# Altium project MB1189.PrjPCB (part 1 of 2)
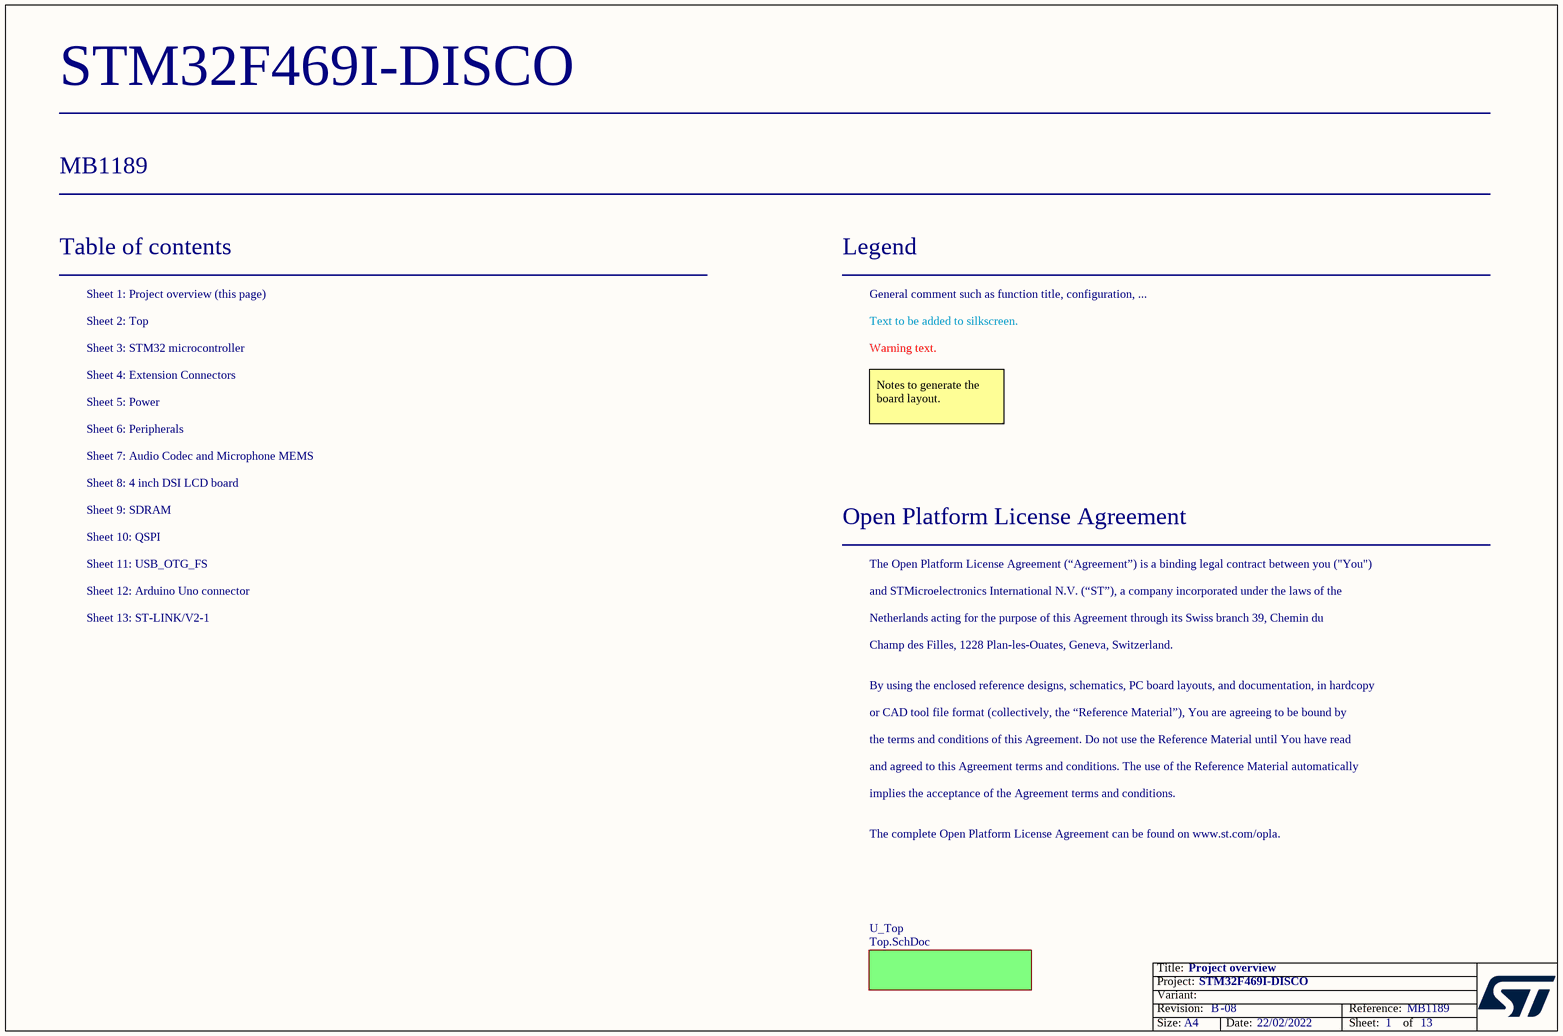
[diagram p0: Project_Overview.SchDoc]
Board_Reference: MB1189; Board_PCB_revision: B; Board_Name: STM32F469I-DISCO; Board_Document_Date: 22/02/2022; Board_Assembly_revision: 08
13 sheets, 276 parts. Net scope: flat (ports and power ports of the same name join across sheets).
Sheets:
  Project_Overview.SchDoc
    U_Top = Top.SchDoc
      U_Memory = Memory.SchDoc
      U_Peripherals = Peripherals.SchDoc
      U_Power = Power.SchDoc
      U_ST_LINK_V2-1 = ST_LINK_V2-1.SCHDOC
      U_MCU = MCU.SchDoc
      U_Arduino_ Connectors = Arduino_ Connectors.SchDoc
      U_DSI_LCD = DSI_LCD.SchDoc
      U_QSPI = QSPI.SchDoc
      U_AUDIO2 = AUDIO2.SchDoc
      U_USB_OTG_FS = USB_OTG_FS.SchDoc
      U_ExtensionConnector = ExtensionConnector.SchDoc

## Sheet Project_Overview.SchDoc: Project overview
size A4; Date: Not used; ApprovedBy: Not used; CheckedBy: Not used; Author: Not used; CompanyName: STMicroelectronics; DrawnBy: Not used; Engineer: Not used; Organization: Not used; Address1: Not used; Address2: Not used; Address3: Not used; Address4: Not used; DocumentNumber: 1; Revision: Not used; SheetNumber: 1; SheetTotal: 13

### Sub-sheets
U_Top = Top.SchDoc: no entries

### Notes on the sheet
- Table of contents
- Sheet 1: Project overview (this page)
- Legend
- General comment such as function title, configuration, ...
- Sheet 2: Top
- Sheet 3: STM32 microcontroller
- Sheet 4: Extension Connectors
- Text to be added to silkscreen.
- Warning text.
- Sheet 5: Power
- Sheet 6: Peripherals
- Notes to generate the board layout.
- Sheet 8: 4 inch DSI LCD board
- Sheet 7: Audio Codec and Microphone MEMS
- Sheet 9: SDRAM
- Sheet 11: USB_OTG_FS
- Sheet 10: QSPI
- Open Platform License Agreement
- The Open Platform License Agreement (“Agreement”) is a binding legal contract between you ("You")
- Sheet 13: ST-LINK/V2-1
- Sheet 12: Arduino Uno connector
- and STMicroelectronics International N.V. (“ST”), a company incorporated under the laws of the
- Netherlands acting for the purpose of this Agreement through its Swiss branch 39, Chemin du
- Champ des Filles, 1228 Plan-les-Ouates, Geneva, Switzerland.
- By using the enclosed reference designs, schematics, PC board layouts, and documentation, in hardcopy
- or CAD tool file format (collectively, the “Reference Material”), You are agreeing to be bound by
- the terms and conditions of this Agreement. Do not use the Reference Material until You have read
- and agreed to this Agreement terms and conditions. The use of the Reference Material automatically
- implies the acceptance of the Agreement terms and conditions.
- The complete Open Platform License Agreement can be found on www.st.com/opla.

## Sheet Top.SchDoc: MB1189
size A3; Date: 9/24/2014; Author: P.A.; CompanyName: STMicroelectronics; Organization: Microcontrollers Division; Address1: 12, Rue Jules HOROWITZ; Address2: 38019 Grenoble; Address3: FRANCE; DocumentNumber: 2; Revision: B-07; SheetNumber: 2; SheetTotal: 13; Project: STM32F469I-DISCO
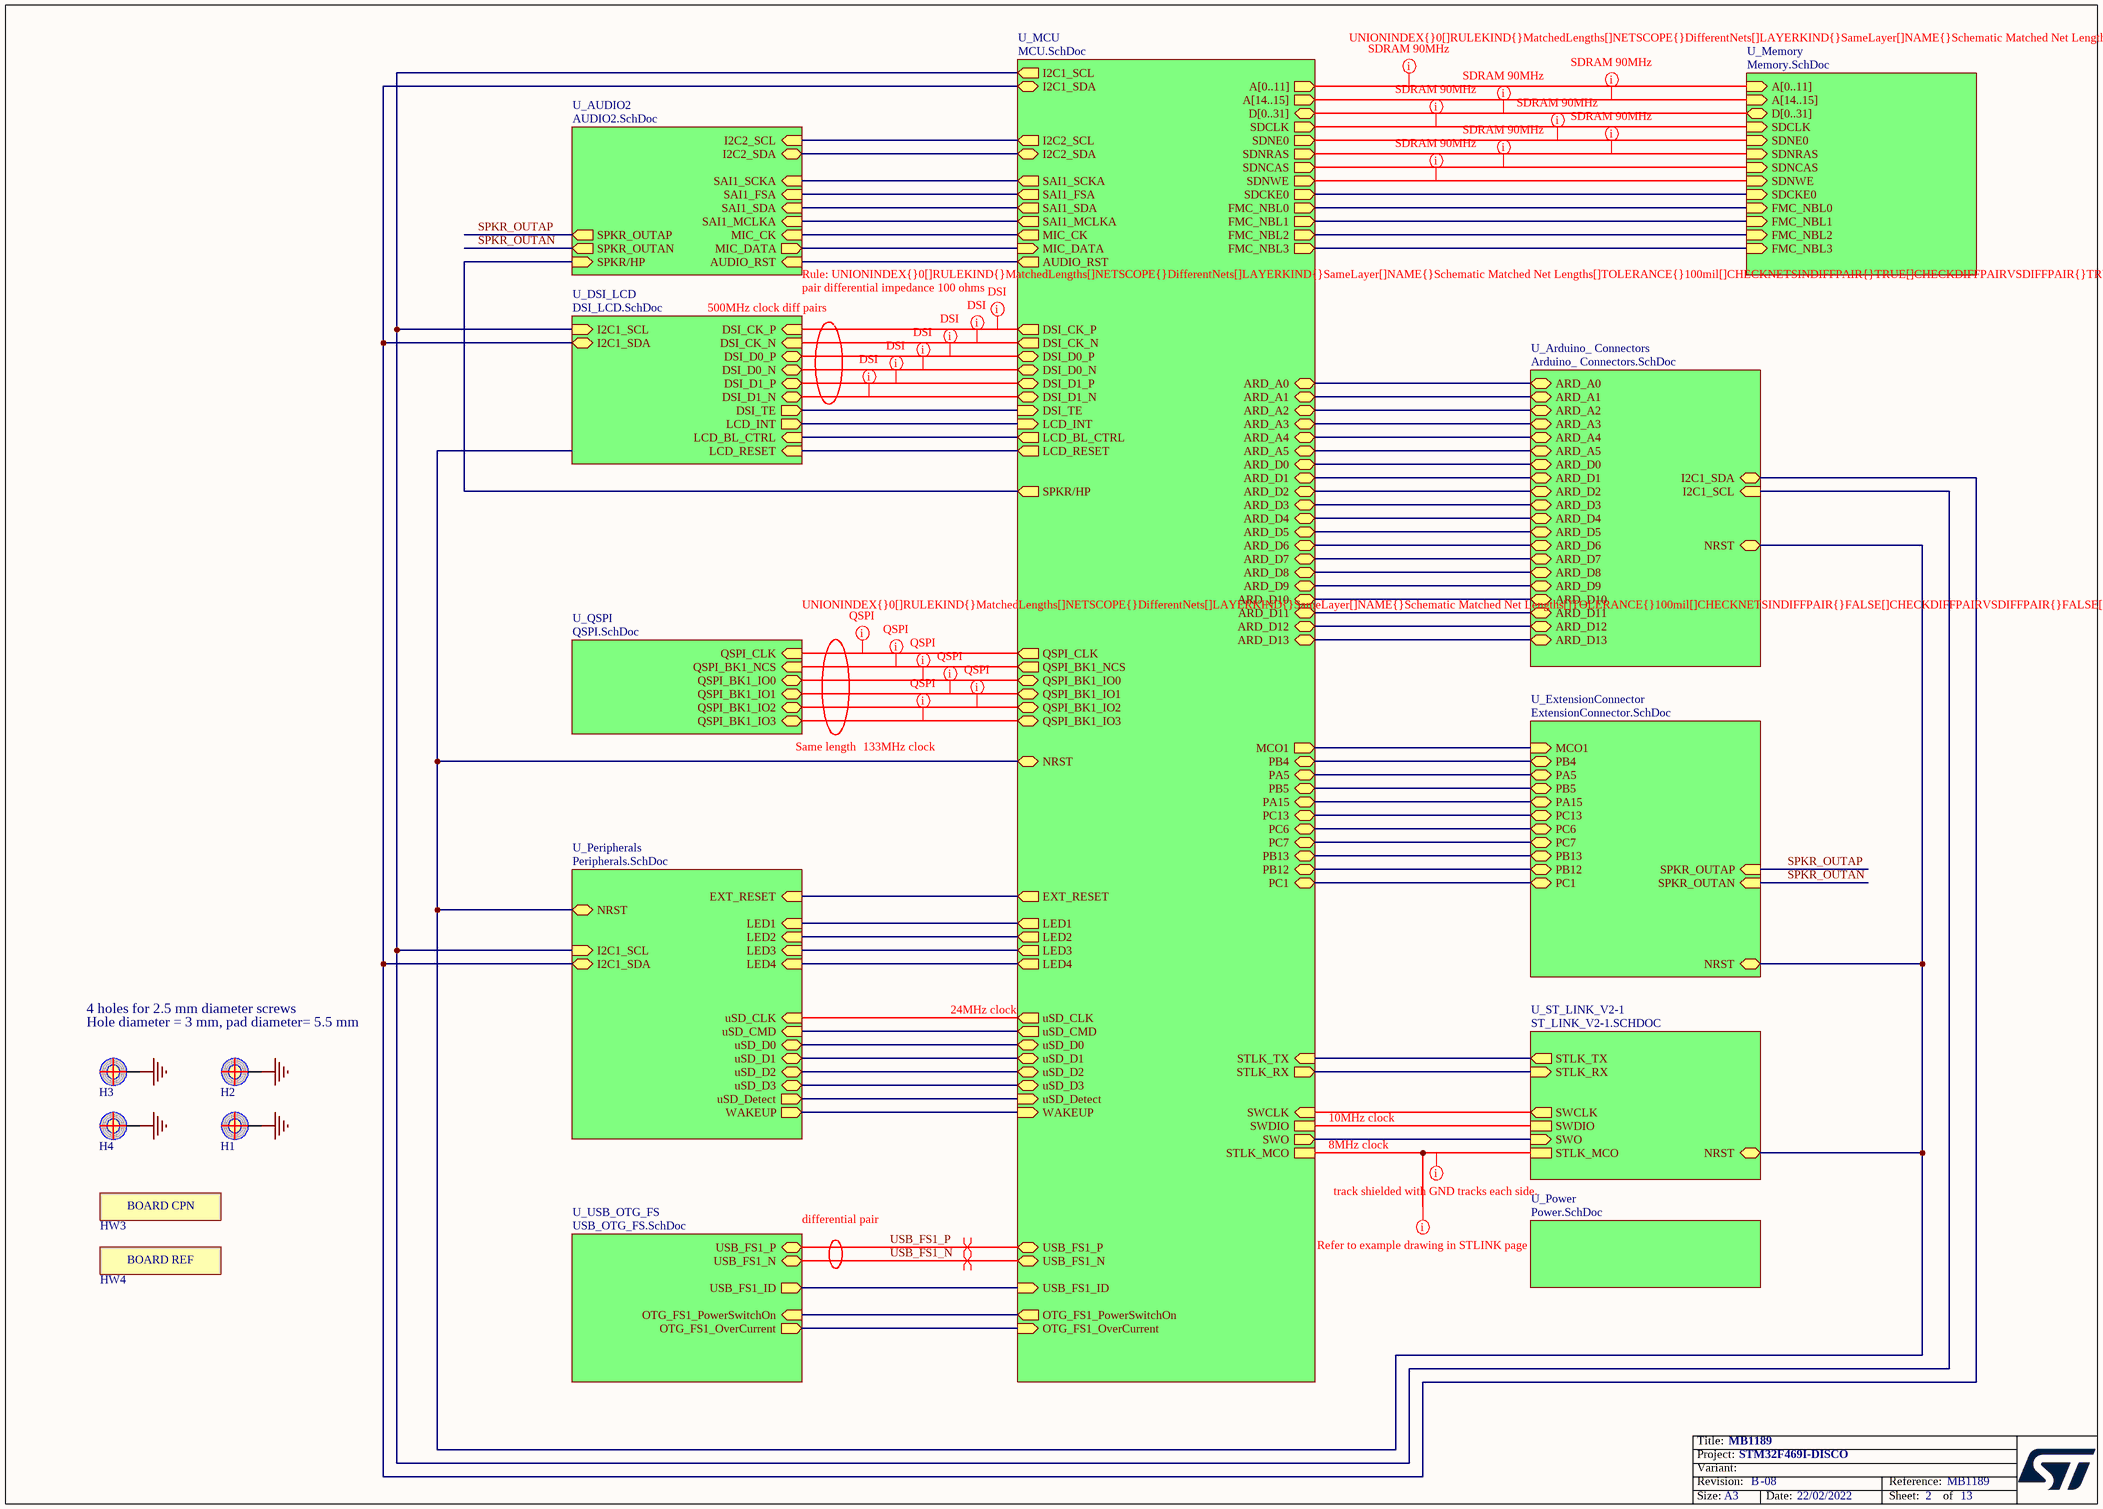
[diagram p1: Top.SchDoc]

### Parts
H1  POSITION HOLE  [HOLE_C5R5D3]  (value not drawn)
H2  POSITION HOLE  [HOLE_C5R5D3]  (value not drawn)
H3  POSITION HOLE  [HOLE_C5R5D3]  (value not drawn)
H4  POSITION HOLE  [HOLE_C5R5D3]  (value not drawn)
HW3  STICKER_BOARD_CPN  [STICKER_BOARD-CPN_13X3]  (value not drawn)  (no BOM)
HW4  STICKER_BOARD_REF  [STICKER_25X9]  (value not drawn)  (no BOM)

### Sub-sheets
U_Arduino_ Connectors = Arduino_ Connectors.SchDoc: I2C1_SDA (bidir), ARD_A0 (bidir), ARD_A1 (bidir), ARD_A2 (bidir), ARD_A3 (bidir), ARD_A4 (bidir), ARD_A5 (bidir), ARD_D5 (bidir), ARD_D4 (bidir), ARD_D3 (bidir), ARD_D2 (bidir), ARD_D1 (bidir), ARD_D0 (bidir), ARD_D13 (bidir), ARD_D12 (bidir), ARD_D11 (bidir), ARD_D10 (bidir), ARD_D9 (bidir), ARD_D8 (bidir), ARD_D6 (bidir), ARD_D7 (bidir), I2C1_SCL (in), NRST (bidir)
U_AUDIO2 = AUDIO2.SchDoc: SAI1_SCKA (in), SAI1_FSA (in), SAI1_SDA (in), AUDIO_RST (in), SAI1_MCLKA (in), I2C2_SCL (in), I2C2_SDA (bidir), MIC_CK (in), MIC_DATA (out), SPKR_OUTAP (out), SPKR_OUTAN (out), SPKR/HP (in)
U_DSI_LCD = DSI_LCD.SchDoc: DSI_CK_P (in), DSI_CK_N (in), DSI_D0_P (bidir), DSI_D0_N (bidir), DSI_D1_P (bidir), DSI_D1_N (bidir), DSI_TE (out), I2C1_SDA (bidir), I2C1_SCL (in), LCD_BL_CTRL (in), LCD_INT (out), LCD_RESET (in)
U_ExtensionConnector = ExtensionConnector.SchDoc: SPKR_OUTAP (in), SPKR_OUTAN (in), NRST (bidir), MCO1 (in), PB4 (bidir), PA5 (bidir), PB5 (bidir), PA15 (bidir), PC13 (bidir), PC7 (bidir), PC6 (bidir), PB13 (bidir), PB12 (bidir), PC1 (bidir)
U_MCU = MCU.SchDoc: LCD_BL_CTRL (out), MIC_CK (out), I2C1_SCL (out), I2C1_SDA (bidir), uSD_D0 (bidir), uSD_D1 (bidir), uSD_D2 (bidir), EXT_RESET (out), uSD_D3 (bidir), uSD_CLK (out), uSD_CMD (out), FMC_NBL3 (out), FMC_NBL2 (out), FMC_NBL0 (out), FMC_NBL1 (out), SAI1_SDA (out), SAI1_SCKA (out), SAI1_FSA (out), SAI1_MCLKA (out), SDNRAS (out), SDCLK (out), SDNCAS (out), SDCKE0 (out), SDNE0 (out), SDNWE (out), D[0..31] (bidir), QSPI_CLK (out), QSPI_BK1_NCS (out), QSPI_BK1_IO3 (bidir), QSPI_BK1_IO2 (bidir), QSPI_BK1_IO1 (bidir), QSPI_BK1_IO0 (bidir), WAKEUP (in), DSI_TE (in), DSI_CK_P (out), DSI_CK_N (out), DSI_D0_P (bidir), DSI_D0_N (bidir), DSI_D1_P (bidir), DSI_D1_N (bidir), NRST (bidir), LCD_INT (in), LED1 (out), LED2 (out), LED3 (out), LED4 (out), uSD_Detect (in), STLK_TX (in), STLK_RX (out), ARD_D5 (bidir), ARD_D4 (bidir), ARD_D3 (bidir), ARD_D2 (bidir), ARD_D1 (bidir), ARD_D0 (bidir), ARD_D13 (bidir), ARD_D12 (bidir), ARD_D11 (bidir), ARD_D10 (bidir), ARD_D9 (bidir), ARD_D8 (bidir), ARD_D6 (bidir), ARD_D7 (bidir), ARD_A0 (bidir), ARD_A1 (bidir), ARD_A2 (bidir), ARD_A3 (bidir), ARD_A4 (bidir), ARD_A5 (bidir), SWCLK (in), SWO (out), AUDIO_RST (out), USB_FS1_ID (in), OTG_FS1_PowerSwitchOn (out), OTG_FS1_OverCurrent (in), I2C2_SCL (out), I2C2_SDA (bidir), MIC_DATA (in), MCO1 (out), USB_FS1_N (bidir), USB_FS1_P (bidir), SWDIO, SPKR/HP (out), A[0..11] (out), A[14..15] (out), PB4 (bidir), PB5 (bidir), PA5 (bidir), PA15 (bidir), PC7 (bidir), PC6 (bidir), PC13 (bidir), PB12 (bidir), PB13 (bidir), PC1 (bidir), LCD_RESET (out), STLK_MCO
U_Memory = Memory.SchDoc: FMC_NBL0 (in), FMC_NBL1 (in), D[0..31] (bidir), SDNCAS (in), SDNWE (in), SDNRAS (in), SDNE0 (in), SDCKE0 (in), SDCLK (in), FMC_NBL3 (in), FMC_NBL2 (in), A[0..11] (in), A[14..15] (in)
U_Peripherals = Peripherals.SchDoc: uSD_CLK (in), uSD_CMD (in), uSD_D0 (bidir), uSD_D1 (bidir), uSD_D2 (bidir), uSD_D3 (bidir), WAKEUP (out), EXT_RESET (in), LED1 (in), LED2 (in), LED3 (in), LED4 (in), NRST (bidir), uSD_Detect (out), I2C1_SDA (bidir), I2C1_SCL (in)
U_Power = Power.SchDoc: no entries
U_QSPI = QSPI.SchDoc: QSPI_BK1_IO0 (bidir), QSPI_BK1_IO2 (bidir), QSPI_BK1_IO1 (bidir), QSPI_CLK (in), QSPI_BK1_NCS (in), QSPI_BK1_IO3 (bidir)
U_ST_LINK_V2-1 = ST_LINK_V2-1.SCHDOC: STLK_RX (in), STLK_TX (out), SWDIO, SWO (in), SWCLK (out), NRST (bidir), STLK_MCO
U_USB_OTG_FS = USB_OTG_FS.SchDoc: OTG_FS1_PowerSwitchOn (in), OTG_FS1_OverCurrent (out), USB_FS1_ID (out), USB_FS1_N (bidir), USB_FS1_P (bidir)

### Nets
GND: H1.1 H2.1 H3.1 H4.1
SPKR_OUTAN: sheet U_AUDIO2/SPKR_OUTAN, sheet U_ExtensionConnector/SPKR_OUTAN
SPKR_OUTAP: sheet U_AUDIO2/SPKR_OUTAP, sheet U_ExtensionConnector/SPKR_OUTAP
USB_FS1_N: sheet U_MCU/USB_FS1_N, sheet U_USB_OTG_FS/USB_FS1_N
USB_FS1_P: sheet U_MCU/USB_FS1_P, sheet U_USB_OTG_FS/USB_FS1_P
(unnamed): sheet U_Memory/FMC_NBL0, sheet U_MCU/FMC_NBL0
(unnamed): sheet U_Memory/FMC_NBL1, sheet U_MCU/FMC_NBL1  [a separate net that carries the same name]
(unnamed): sheet U_Memory/SDNCAS, sheet U_MCU/SDNCAS  [a separate net that carries the same name]
(unnamed): sheet U_Memory/SDNWE, sheet U_MCU/SDNWE  [a separate net that carries the same name]
(unnamed): sheet U_Memory/SDNRAS, sheet U_MCU/SDNRAS  [a separate net that carries the same name]
(unnamed): sheet U_Memory/SDNE0, sheet U_MCU/SDNE0  [a separate net that carries the same name]
(unnamed): sheet U_Memory/SDCKE0, sheet U_MCU/SDCKE0  [a separate net that carries the same name]
(unnamed): sheet U_Memory/SDCLK, sheet U_MCU/SDCLK  [a separate net that carries the same name]
(unnamed): sheet U_Memory/FMC_NBL3, sheet U_MCU/FMC_NBL3  [a separate net that carries the same name]
(unnamed): sheet U_Memory/FMC_NBL2, sheet U_MCU/FMC_NBL2  [a separate net that carries the same name]
(unnamed): sheet U_Peripherals/uSD_CLK, sheet U_MCU/uSD_CLK  [a separate net that carries the same name]
(unnamed): sheet U_Peripherals/uSD_CMD, sheet U_MCU/uSD_CMD  [a separate net that carries the same name]
(unnamed): sheet U_Peripherals/uSD_D0, sheet U_MCU/uSD_D0  [a separate net that carries the same name]
(unnamed): sheet U_Peripherals/uSD_D1, sheet U_MCU/uSD_D1  [a separate net that carries the same name]
(unnamed): sheet U_Peripherals/uSD_D2, sheet U_MCU/uSD_D2  [a separate net that carries the same name]
(unnamed): sheet U_Peripherals/uSD_D3, sheet U_MCU/uSD_D3  [a separate net that carries the same name]
(unnamed): sheet U_Peripherals/WAKEUP, sheet U_MCU/WAKEUP  [a separate net that carries the same name]
(unnamed): sheet U_Peripherals/EXT_RESET, sheet U_MCU/EXT_RESET  [a separate net that carries the same name]
(unnamed): sheet U_Peripherals/LED1, sheet U_MCU/LED1  [a separate net that carries the same name]
(unnamed): sheet U_Peripherals/LED2, sheet U_MCU/LED2  [a separate net that carries the same name]
(unnamed): sheet U_Peripherals/LED3, sheet U_MCU/LED3  [a separate net that carries the same name]
(unnamed): sheet U_Peripherals/LED4, sheet U_MCU/LED4  [a separate net that carries the same name]
(unnamed): sheet U_Peripherals/NRST, sheet U_ST_LINK_V2-1/NRST, sheet U_MCU/NRST, sheet U_Arduino_ Connectors/NRST, sheet U_ExtensionConnector/NRST  [a separate net that carries the same name]
(unnamed): sheet U_Peripherals/uSD_Detect, sheet U_MCU/uSD_Detect  [a separate net that carries the same name]
(unnamed): sheet U_Peripherals/I2C1_SDA, sheet U_MCU/I2C1_SDA, sheet U_Arduino_ Connectors/I2C1_SDA, sheet U_DSI_LCD/I2C1_SDA  [a separate net that carries the same name]
(unnamed): sheet U_Peripherals/I2C1_SCL, sheet U_MCU/I2C1_SCL, sheet U_Arduino_ Connectors/I2C1_SCL, sheet U_DSI_LCD/I2C1_SCL  [a separate net that carries the same name]
(unnamed): sheet U_ST_LINK_V2-1/STLK_RX, sheet U_MCU/STLK_RX  [a separate net that carries the same name]
(unnamed): sheet U_ST_LINK_V2-1/STLK_TX, sheet U_MCU/STLK_TX  [a separate net that carries the same name]
(unnamed): sheet U_ST_LINK_V2-1/SWDIO, sheet U_MCU/SWDIO  [a separate net that carries the same name]
(unnamed): sheet U_ST_LINK_V2-1/SWO, sheet U_MCU/SWO  [a separate net that carries the same name]
(unnamed): sheet U_ST_LINK_V2-1/SWCLK, sheet U_MCU/SWCLK  [a separate net that carries the same name]
(unnamed): sheet U_ST_LINK_V2-1/STLK_MCO, sheet U_MCU/STLK_MCO  [a separate net that carries the same name]
(unnamed): sheet U_MCU/LCD_BL_CTRL, sheet U_DSI_LCD/LCD_BL_CTRL  [a separate net that carries the same name]
(unnamed): sheet U_MCU/MIC_CK, sheet U_AUDIO2/MIC_CK  [a separate net that carries the same name]
(unnamed): sheet U_MCU/SAI1_SDA, sheet U_AUDIO2/SAI1_SDA  [a separate net that carries the same name]
(unnamed): sheet U_MCU/SAI1_SCKA, sheet U_AUDIO2/SAI1_SCKA  [a separate net that carries the same name]
(unnamed): sheet U_MCU/SAI1_FSA, sheet U_AUDIO2/SAI1_FSA  [a separate net that carries the same name]
(unnamed): sheet U_MCU/SAI1_MCLKA, sheet U_AUDIO2/SAI1_MCLKA  [a separate net that carries the same name]
(unnamed): sheet U_MCU/QSPI_CLK, sheet U_QSPI/QSPI_CLK  [a separate net that carries the same name]
(unnamed): sheet U_MCU/QSPI_BK1_NCS, sheet U_QSPI/QSPI_BK1_NCS  [a separate net that carries the same name]
(unnamed): sheet U_MCU/QSPI_BK1_IO3, sheet U_QSPI/QSPI_BK1_IO3  [a separate net that carries the same name]
(unnamed): sheet U_MCU/QSPI_BK1_IO2, sheet U_QSPI/QSPI_BK1_IO2  [a separate net that carries the same name]
(unnamed): sheet U_MCU/QSPI_BK1_IO1, sheet U_QSPI/QSPI_BK1_IO1  [a separate net that carries the same name]
(unnamed): sheet U_MCU/QSPI_BK1_IO0, sheet U_QSPI/QSPI_BK1_IO0  [a separate net that carries the same name]
(unnamed): sheet U_MCU/DSI_TE, sheet U_DSI_LCD/DSI_TE  [a separate net that carries the same name]
(unnamed): sheet U_MCU/DSI_CK_P, sheet U_DSI_LCD/DSI_CK_P  [a separate net that carries the same name]
(unnamed): sheet U_MCU/DSI_CK_N, sheet U_DSI_LCD/DSI_CK_N  [a separate net that carries the same name]
(unnamed): sheet U_MCU/DSI_D0_P, sheet U_DSI_LCD/DSI_D0_P  [a separate net that carries the same name]
(unnamed): sheet U_MCU/DSI_D0_N, sheet U_DSI_LCD/DSI_D0_N  [a separate net that carries the same name]
(unnamed): sheet U_MCU/DSI_D1_P, sheet U_DSI_LCD/DSI_D1_P  [a separate net that carries the same name]
(unnamed): sheet U_MCU/DSI_D1_N, sheet U_DSI_LCD/DSI_D1_N  [a separate net that carries the same name]
(unnamed): sheet U_MCU/LCD_INT, sheet U_DSI_LCD/LCD_INT  [a separate net that carries the same name]
(unnamed): sheet U_MCU/ARD_D5, sheet U_Arduino_ Connectors/ARD_D5  [a separate net that carries the same name]
(unnamed): sheet U_MCU/ARD_D4, sheet U_Arduino_ Connectors/ARD_D4  [a separate net that carries the same name]
(unnamed): sheet U_MCU/ARD_D3, sheet U_Arduino_ Connectors/ARD_D3  [a separate net that carries the same name]
(unnamed): sheet U_MCU/ARD_D2, sheet U_Arduino_ Connectors/ARD_D2  [a separate net that carries the same name]
(unnamed): sheet U_MCU/ARD_D1, sheet U_Arduino_ Connectors/ARD_D1  [a separate net that carries the same name]
(unnamed): sheet U_MCU/ARD_D0, sheet U_Arduino_ Connectors/ARD_D0  [a separate net that carries the same name]
(unnamed): sheet U_MCU/ARD_D13, sheet U_Arduino_ Connectors/ARD_D13  [a separate net that carries the same name]
(unnamed): sheet U_MCU/ARD_D12, sheet U_Arduino_ Connectors/ARD_D12  [a separate net that carries the same name]
(unnamed): sheet U_MCU/ARD_D11, sheet U_Arduino_ Connectors/ARD_D11  [a separate net that carries the same name]
(unnamed): sheet U_MCU/ARD_D10, sheet U_Arduino_ Connectors/ARD_D10  [a separate net that carries the same name]
(unnamed): sheet U_MCU/ARD_D9, sheet U_Arduino_ Connectors/ARD_D9  [a separate net that carries the same name]
(unnamed): sheet U_MCU/ARD_D8, sheet U_Arduino_ Connectors/ARD_D8  [a separate net that carries the same name]
(unnamed): sheet U_MCU/ARD_D6, sheet U_Arduino_ Connectors/ARD_D6  [a separate net that carries the same name]
(unnamed): sheet U_MCU/ARD_D7, sheet U_Arduino_ Connectors/ARD_D7  [a separate net that carries the same name]
(unnamed): sheet U_MCU/ARD_A0, sheet U_Arduino_ Connectors/ARD_A0  [a separate net that carries the same name]
(unnamed): sheet U_MCU/ARD_A1, sheet U_Arduino_ Connectors/ARD_A1  [a separate net that carries the same name]
(unnamed): sheet U_MCU/ARD_A2, sheet U_Arduino_ Connectors/ARD_A2  [a separate net that carries the same name]
(unnamed): sheet U_MCU/ARD_A3, sheet U_Arduino_ Connectors/ARD_A3  [a separate net that carries the same name]
(unnamed): sheet U_MCU/ARD_A4, sheet U_Arduino_ Connectors/ARD_A4  [a separate net that carries the same name]
(unnamed): sheet U_MCU/ARD_A5, sheet U_Arduino_ Connectors/ARD_A5  [a separate net that carries the same name]
(unnamed): sheet U_MCU/AUDIO_RST, sheet U_AUDIO2/AUDIO_RST  [a separate net that carries the same name]
(unnamed): sheet U_MCU/USB_FS1_ID, sheet U_USB_OTG_FS/USB_FS1_ID  [a separate net that carries the same name]
(unnamed): sheet U_MCU/OTG_FS1_PowerSwitchOn, sheet U_USB_OTG_FS/OTG_FS1_PowerSwitchOn  [a separate net that carries the same name]
(unnamed): sheet U_MCU/OTG_FS1_OverCurrent, sheet U_USB_OTG_FS/OTG_FS1_OverCurrent  [a separate net that carries the same name]
(unnamed): sheet U_MCU/I2C2_SCL, sheet U_AUDIO2/I2C2_SCL  [a separate net that carries the same name]
(unnamed): sheet U_MCU/I2C2_SDA, sheet U_AUDIO2/I2C2_SDA  [a separate net that carries the same name]
(unnamed): sheet U_MCU/MIC_DATA, sheet U_AUDIO2/MIC_DATA  [a separate net that carries the same name]
(unnamed): sheet U_MCU/MCO1, sheet U_ExtensionConnector/MCO1  [a separate net that carries the same name]
(unnamed): sheet U_MCU/SPKR/HP, sheet U_AUDIO2/SPKR/HP  [a separate net that carries the same name]
(unnamed): sheet U_MCU/PB4, sheet U_ExtensionConnector/PB4  [a separate net that carries the same name]
(unnamed): sheet U_MCU/PB5, sheet U_ExtensionConnector/PB5  [a separate net that carries the same name]
(unnamed): sheet U_MCU/PA5, sheet U_ExtensionConnector/PA5  [a separate net that carries the same name]
(unnamed): sheet U_MCU/PA15, sheet U_ExtensionConnector/PA15  [a separate net that carries the same name]
(unnamed): sheet U_MCU/PC7, sheet U_ExtensionConnector/PC7  [a separate net that carries the same name]
(unnamed): sheet U_MCU/PC6, sheet U_ExtensionConnector/PC6  [a separate net that carries the same name]
(unnamed): sheet U_MCU/PC13, sheet U_ExtensionConnector/PC13  [a separate net that carries the same name]
(unnamed): sheet U_MCU/PB12, sheet U_ExtensionConnector/PB12  [a separate net that carries the same name]
(unnamed): sheet U_MCU/PB13, sheet U_ExtensionConnector/PB13  [a separate net that carries the same name]
(unnamed): sheet U_MCU/PC1, sheet U_ExtensionConnector/PC1  [a separate net that carries the same name]
(unnamed): sheet U_MCU/LCD_RESET, sheet U_DSI_LCD/LCD_RESET  [a separate net that carries the same name]

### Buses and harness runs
bus sheet U_MCU/A[0..11] = sheet U_Memory/A[0..11]
bus sheet U_MCU/A[14..15] = sheet U_Memory/A[14..15]
bus sheet U_MCU/D[0..31] = sheet U_Memory/D[0..31]

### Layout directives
rule Matched Net Lengths [Tolerance = 250mil]: (no net found under the mark)
rule Matched Net Lengths [Tolerance = 100mil]; rule ? : (no net found under the mark)
rule Matched Net Lengths [Tolerance = 100mil]: (no net found under the mark)
differential pair: USB_FS1_N, USB_FS1_P
mark named track shielded with GND tracks each side.: (no net found under the mark)
mark named Refer to example drawing in STLINK page: (no net found under the mark)

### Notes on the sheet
- 500MHz clock diff pairs
- Same length
- 133MHz clock
- 4 holes for 2.5 mm diameter screws
- Hole diameter = 3 mm, pad diameter= 5.5 mm
- 24MHz clock
- 10MHz clock
- 8MHz clock
- differential pair

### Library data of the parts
H1-H4 = POSITION HOLE: Ordered by: Subcon

## Sheet Memory.SchDoc: SDRAM
size A4; Date: 9/24/2014; Author: P.A.; CompanyName: STMicroelectronics; Organization: Microcontrollers Division; Address1: 12, Rue Jules HOROWITZ; Address2: 38019 Grenoble; Address3: FRANCE; DocumentNumber: 9; Revision: B-07; SheetNumber: 9; SheetTotal: 13; Project: STM32F469I-DISCO
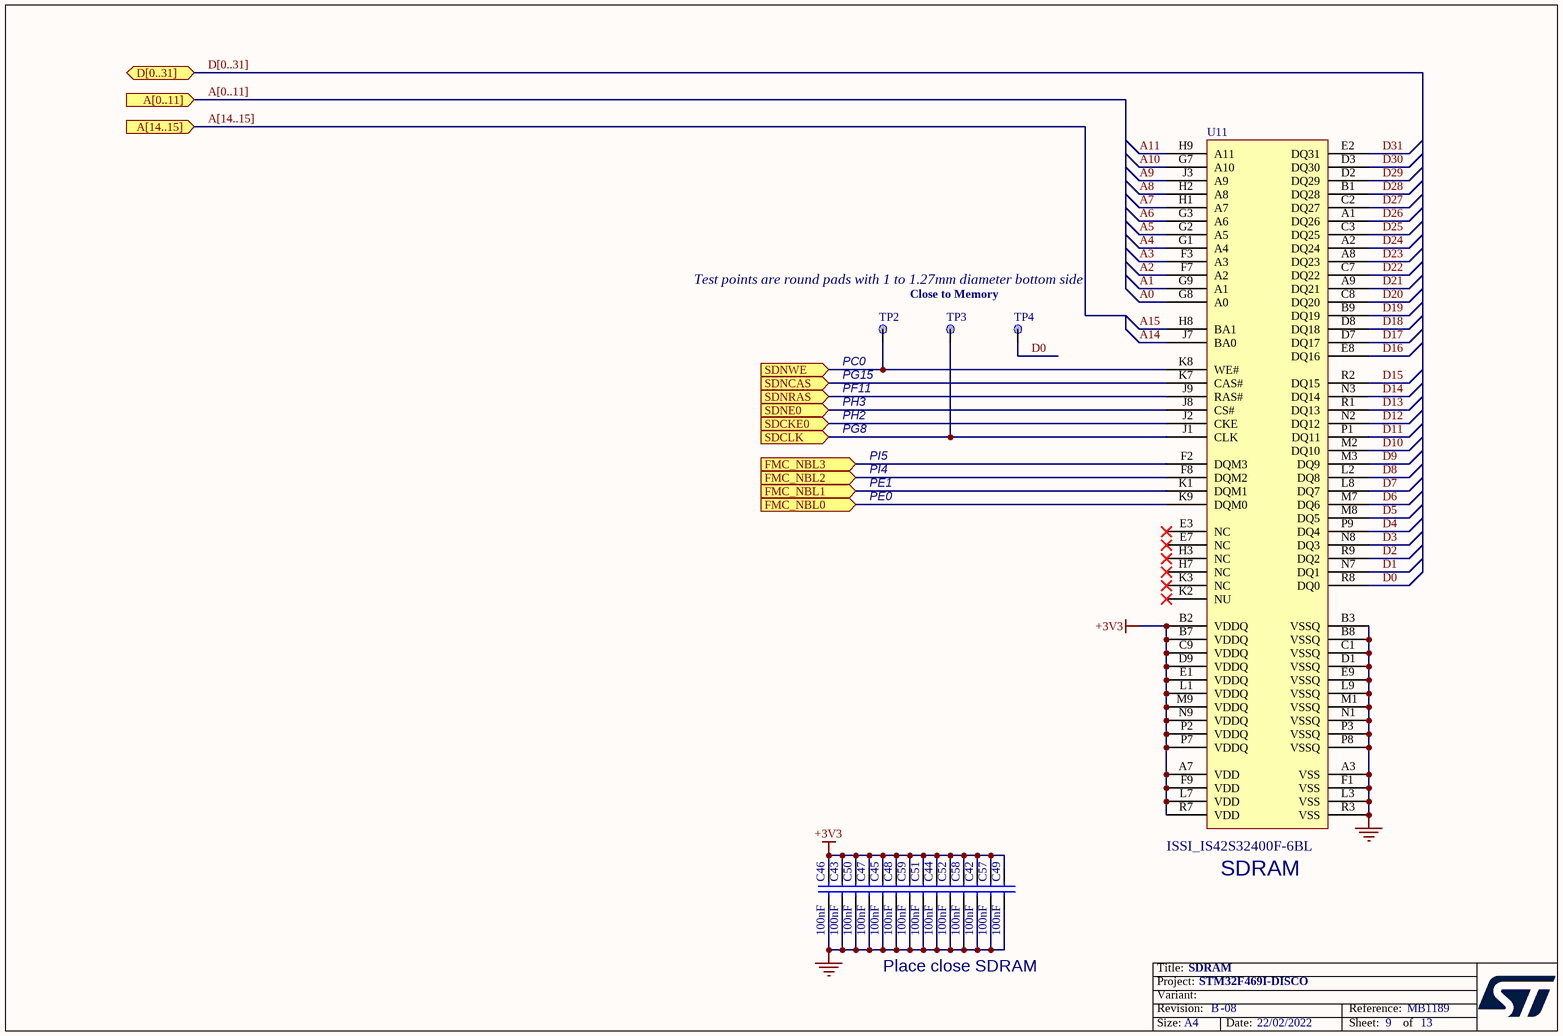
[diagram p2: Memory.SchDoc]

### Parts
C42  100nF  [0402C]
C43  100nF  [0402C]
C44  100nF  [0402C]
C45  100nF  [0402C]
C46  100nF  [0402C]
C47  100nF  [0402C]
C48  100nF  [0402C]
C49  100nF  [0402C]
C50  100nF  [0402C]
C51  100nF  [0402C]
C52  100nF  [0402C]
C57  100nF  [0402C]
C58  100nF  [0402C]
C59  100nF  [0402C]
TP2  TP  [TP_C40]  (value not drawn)
TP3  TP  [TP_C40]  (value not drawn)
TP4  TP  [TP_C40]  (value not drawn)
U11  ISSI_IS42S32400F-6BL  [FBGA90_0R8_8X13]

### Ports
A[0..11] (in), A[14..15] (in), D[0..31] (bidir), FMC_NBL0 (in), FMC_NBL1 (in), FMC_NBL2 (in), FMC_NBL3 (in), SDCKE0 (in), SDCLK (in), SDNCAS (in), SDNE0 (in), SDNRAS (in), SDNWE (in)

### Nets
+3V3: C42.1 C43.1 C44.1 C45.1 C46.1 C47.1 C48.1 C49.1 C50.1 C51.1 C52.1 C57.1 C58.1 C59.1 U11.A7(VDD) U11.B2(VDDQ) U11.B7(VDDQ) U11.C9(VDDQ) U11.D9(VDDQ) U11.E1(VDDQ) U11.F9(VDD) U11.L1(VDDQ) U11.L7(VDD) U11.M9(VDDQ) U11.N9(VDDQ) U11.P2(VDDQ) U11.P7(VDDQ) U11.R7(VDD)
GND: C42.2 C43.2 C44.2 C45.2 C46.2 C47.2 C48.2 C49.2 C50.2 C51.2 C52.2 C57.2 C58.2 C59.2 U11.A3(VSS) U11.B3(VSSQ) U11.B8(VSSQ) U11.C1(VSSQ) U11.D1(VSSQ) U11.E9(VSSQ) U11.F1(VSS) U11.L3(VSS) U11.L9(VSSQ) U11.M1(VSSQ) U11.N1(VSSQ) U11.P3(VSSQ) U11.P8(VSSQ) U11.R3(VSS)
A0: U11.G8(A0)
A1: U11.G9(A1)
A2: U11.F7(A2)
A3: U11.F3(A3)
A4: U11.G1(A4)
A5: U11.G2(A5)
A6: U11.G3(A6)
A7: U11.H1(A7)
A8: U11.H2(A8)
A9: U11.J3(A9)
A10: U11.G7(A10)
A11: U11.H9(A11)
A14: U11.J7(BA0)
A15: U11.H8(BA1)
D0: TP4.1 U11.R8(DQ0)
D1: U11.N7(DQ1)
D2: U11.R9(DQ2)
D3: U11.N8(DQ3)
D4: U11.P9(DQ4)
D5: U11.M8(DQ5)
D6: U11.M7(DQ6)
D7: U11.L8(DQ7)
D8: U11.L2(DQ8)
D9: U11.M3(DQ9)
D10: U11.M2(DQ10)
D11: U11.P1(DQ11)
D12: U11.N2(DQ12)
D13: U11.R1(DQ13)
D14: U11.N3(DQ14)
D15: U11.R2(DQ15)
D16: U11.E8(DQ16)
D17: U11.D7(DQ17)
D18: U11.D8(DQ18)
D19: U11.B9(DQ19)
D20: U11.C8(DQ20)
D21: U11.A9(DQ21)
D22: U11.C7(DQ22)
D23: U11.A8(DQ23)
D24: U11.A2(DQ24)
D25: U11.C3(DQ25)
D26: U11.A1(DQ26)
D27: U11.C2(DQ27)
D28: U11.B1(DQ28)
D29: U11.D2(DQ29)
D30: U11.D3(DQ30)
D31: U11.E2(DQ31)
PC0: TP2.1 U11.K8(WE#) ; port SDNWE
PE0: U11.K9(DQM0) ; port FMC_NBL0
PE1: U11.K1(DQM1) ; port FMC_NBL1
PF11: U11.J9(RAS#) ; port SDNRAS
PG8: TP3.1 U11.J1(CLK) ; port SDCLK
PG15: U11.K7(CAS#) ; port SDNCAS
PH2: U11.J2(CKE) ; port SDCKE0
PH3: U11.J8(CS#) ; port SDNE0
PI4: U11.F8(DQM2) ; port FMC_NBL2
PI5: U11.F2(DQM3) ; port FMC_NBL3

Not connected (* = marked no-connect by the designer): U11 E3(NC)* E7(NC)* H3(NC)* H7(NC)* K2(NU)* K3(NC)*

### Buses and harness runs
bus A[0..11] = port A[0..11]
bus A[14..15] = port A[14..15]
bus D[0..31] = port D[0..31]

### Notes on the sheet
- Test points are round pads with 1 to 1.27mm diameter bottom side
- Close to Memory
- (near TP2) PC0
- (near TP2) PG15
- PF11
- PH3
- PH2
- PG8
- PE1
- PE0
- PI5
- PI4
- (near U11) SDRAM
- Place close SDRAM

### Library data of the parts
C42-C52 C57-C59 = Cap: Capacitor; Value: 10nF; Ordered by: Subcon
TP2-TP4 = TP: Ordered by: Subcon
U11 = MT48LC4M32B2B5: Manuf_1: ISSI; Ordered by: Subcon

## Sheet Peripherals.SchDoc: Peripherals
size A4; Date: 9/24/2014; Author: P.A.; CompanyName: STMicroelectronics; Organization: Microcontrollers Division; Address1: 12, Rue Jules HOROWITZ; Address2: 38019 Grenoble; Address3: FRANCE; DocumentNumber: 6; Revision: B-07; SheetNumber: 6; SheetTotal: 13; Project: STM32F469I-DISCO
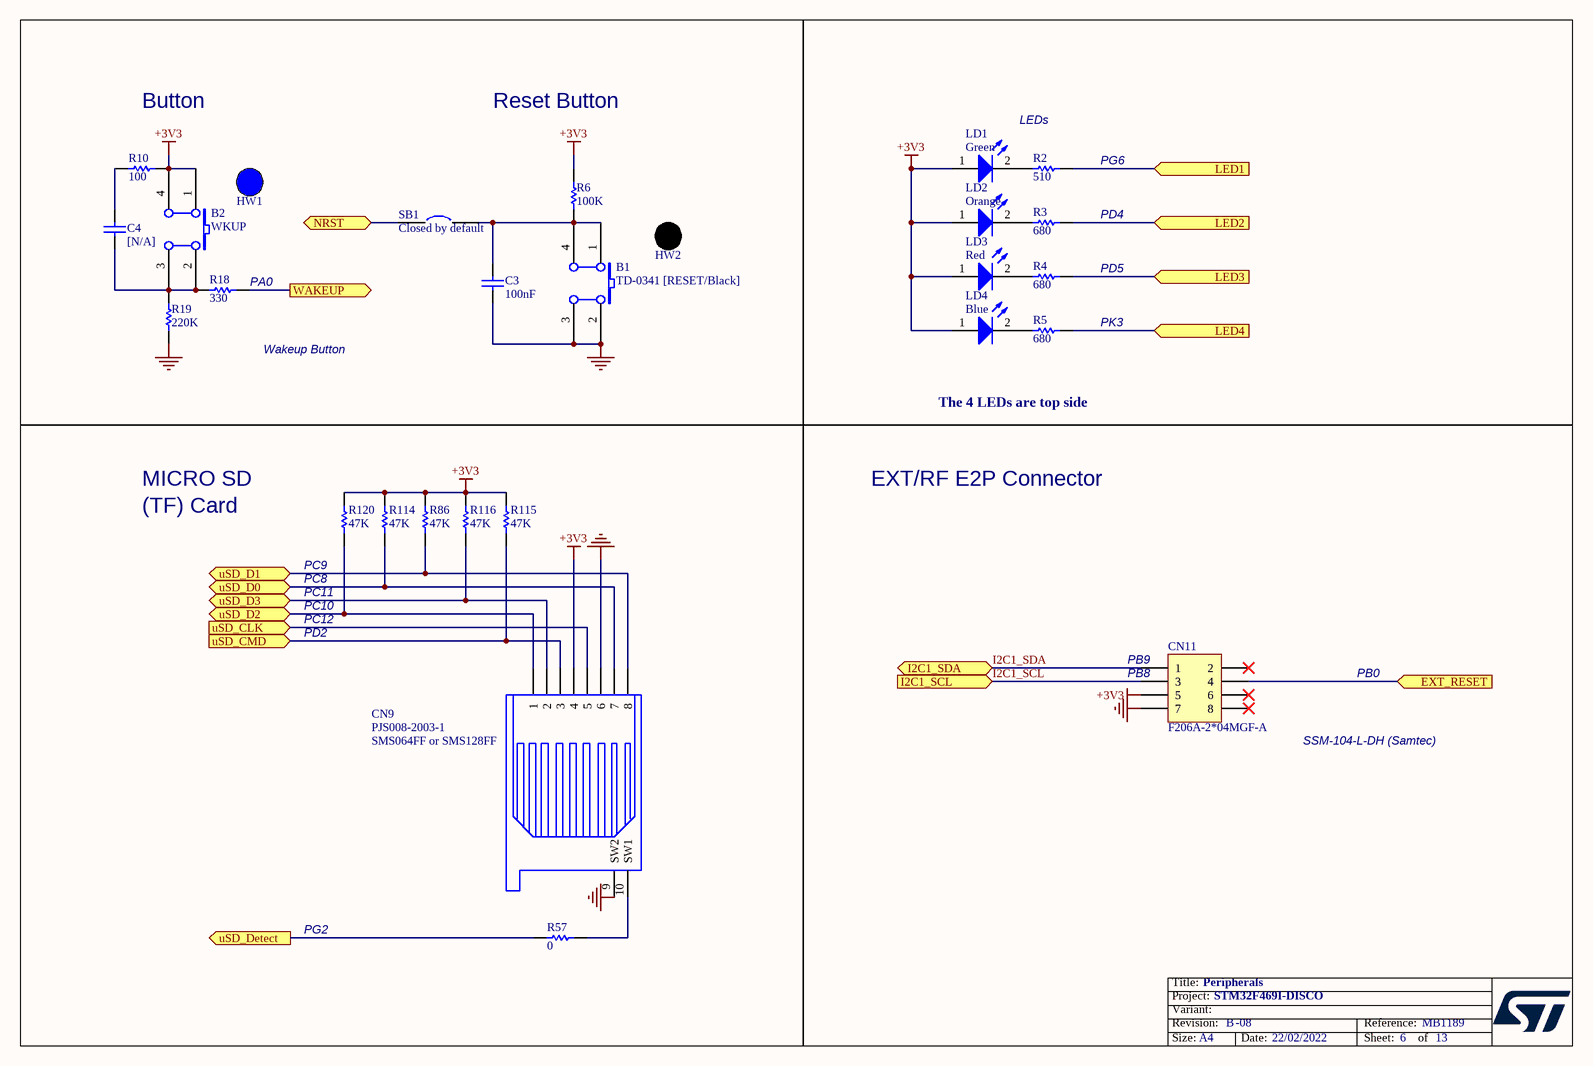
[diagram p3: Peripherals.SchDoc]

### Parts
B1  TD-0341 [RESET/Black]  [PB10]
B2  WKUP  [PB10]
C3  100nF  [0402C]
C4  [N/A]  [0603C]
CN9  PJS008-2003-1  [MSD_PJS008_]
CN11  F206A-2*04MGF-A  [SSM-104-L-DH]
HW1  BUTTON_HAT_BLUE  (value not drawn)  (mechanical)
HW2  BUTTON_HAT_BLACK  (value not drawn)  (mechanical)
LD1  Green  [0603D]
LD2  Orange  [0603D]
LD3  Red  [0603D]
LD4  Blue  [0603D]
R2  510  [0603R]
R3  680  [0603R]
R4  680  [0603R]
R5  680  [0603R]
R6  100K  [0603R]
R10  100  [0603R]
R18  330  [0603R]
R19  220K  [0603R]
R57  0  [0603R]
R86  47K  [0603R]
R114  47K  [0603R]
R115  47K  [0603R]
R116  47K  [0603R]
R120  47K  [0603R]
SB1  Closed by default  [SB_0603]

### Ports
EXT_RESET (in), I2C1_SCL (in), I2C1_SDA (bidir), LED1 (in), LED2 (in), LED3 (in), LED4 (in), NRST (bidir), uSD_CLK (in), uSD_CMD (in), uSD_D0 (bidir), uSD_D1 (bidir), uSD_D2 (bidir), uSD_D3 (bidir), uSD_Detect (out), WAKEUP (out)

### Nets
+3V3: B2.1(A0) B2.4(A1) CN9.4 CN11.5 LD1.1(A) LD2.1(A) LD3.1(A) LD4.1(A) R6.1 R10.1 R86.1 R114.1 R115.1 R116.1 R120.1
GND: B1.2(B0) B1.3(B1) C3.1 CN9.6 CN9.9(SW2) CN11.7 R19.2
I2C1_SCL: CN11.3 ; port I2C1_SCL
I2C1_SDA: CN11.1 ; port I2C1_SDA
NRST: SB1.1 ; port NRST
PA0: R18.2 ; port WAKEUP
PB0: CN11.4 ; port EXT_RESET
PC8: CN9.7 R114.2 ; port uSD_D0
PC10: CN9.1 R120.2 ; port uSD_D2
PC11: CN9.2 R116.2 ; port uSD_D3
PC12: CN9.5 ; port uSD_CLK
PD2: CN9.3 R115.2 ; port uSD_CMD
PD4: R3.1 ; port LED2
PD5: R4.1 ; port LED3
PG2: R57.1 ; port uSD_Detect
PG6: R2.1 ; port LED1
PK3: R5.1 ; port LED4
NetB1_1: B1.1(A0) B1.4(A1) C3.2 R6.2 SB1.2
NetB2_2: B2.2(B0) B2.3(B1) C4.2 R18.1 R19.1
NetC4_1: C4.1 R10.2
NetCN9_8: CN9.8 R86.2 ; port uSD_D1
NetCN9_10: CN9.10(SW1) R57.2
NetLD1_2: LD1.2(K) R2.2
NetLD2_2: LD2.2(K) R3.2
NetLD3_2: LD3.2(K) R4.2
NetLD4_2: LD4.2(K) R5.2

Not connected (* = marked no-connect by the designer): CN11 2* 6* 8*

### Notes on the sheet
- Button
- Reset Button
- LEDs
- (near R2) PG6
- PD4
- (near R18) PA0
- PD5
- PK3
- Wakeup Button
- The 4 LEDs are top side
- MICRO SD
- (TF) Card
- EXT/RF E2P Connector
- (near R120) PC8
- (near R120) PC9
- PC11
- PC10
- PC12
- PD2
- (near CN11) PB9
- (near CN11) PB8
- PB0
- (near CN9) SMS064FF or SMS128FF
- (near CN11) SSM-104-L-DH (Samtec)
- PG2

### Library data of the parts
B1 = SW PUSHBUTTON: SE PUSHBUTTON; Ordered by: Subcon; Assembly: with Back cap; Silkscreen: RESET
B2 = SW PUSHBUTTON: SE PUSHBUTTON; Ordered by: Subcon; Assembly: with Blue cap; Silkscreen: USER
C3 = CAP: Capacitor; Value: 100pF; Ordered by: Subcon
C4 = CAP: Capacitor; Value: 100pF; Ordered by: Subcon; Fitted: NO
CN9 = SMS016AFA5E: Manuf_1: Yamaichi; Ordered by: Subcon; Silkscreen: uSD
CN11 = SSM-104-L-DH: Header, 4-Pin, Dual row; Manuf_1: SAMTEC; Ordered by: Subcon; Silkscreen: RFEEPROM
HW1 = BUTTON_HAT_BLUE: switch hat,blue; Manuf_part_1: KTSC-62B; Manuf_1: CHAU HUA
HW2 = BUTTON_HAT_BLACK: switch hat,black; Manuf_part_1: KTSC-62K; Manuf_1: CHAU HUA
LD1-LD4 = LED2: Typical RED, GREEN, YELLOW, AMBER GaAs LED; Ordered by: Subcon; ECCN_US/EU: EAR99/NEC
R2-R5 R10 R18 R57 = Res1: Resistor; Value: 1K; Ordered by: Subcon
R6 R19 R86 R114-R116 R120 = res1: Resistor; Value: 1K; Ordered by: Subcon
SB1 = Circuit Breaker: Ordered by: Subcon; Comments: Solder bridge

## Sheet Power.SchDoc: Power
size A4; Date: 9/24/2014; Author: P.A.; CompanyName: STMicroelectronics; Organization: Microcontrollers Division; Address1: 12, Rue Jules HOROWITZ; Address2: 38019 Grenoble; Address3: FRANCE; DocumentNumber: 5; Revision: B-07; SheetNumber: 5; SheetTotal: 13; Project: STM32F469I-DISCO
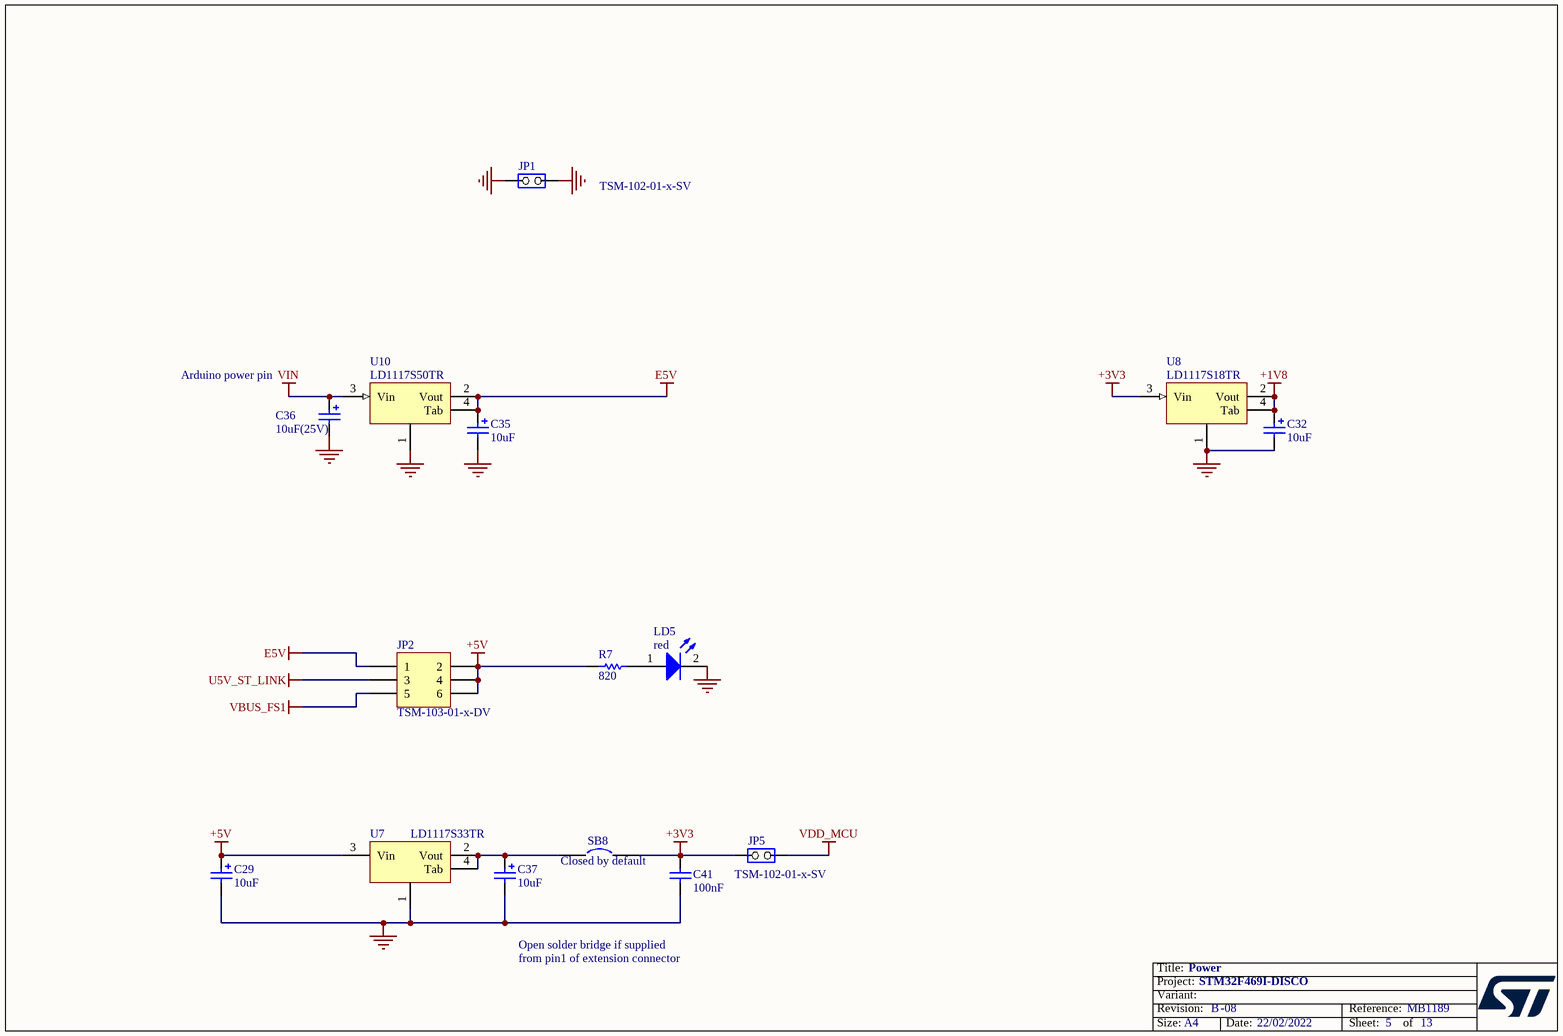
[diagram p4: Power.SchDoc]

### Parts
C29  10uF  [TAN-A]
C32  10uF  [TAN-A]
C35  10uF  [TAN-A]
C36  10uF(25V)  [TAN-B]
C37  10uF  [TAN-A]
C41  100nF  [0402C]
JP1  TSM-102-01-x-SV  [TSM-102-01-x-SV]
JP2  TSM-103-01-x-DV  [TSM-103-01-x-DV]
JP5  TSM-102-01-x-SV  [TSM-102-01-x-SV]
LD5  red  [0603D]
R7  820  [0603R]
SB8  Closed by default  [SB_0603]
U7  LD1117S33TR  [SOT-223]
U8  LD1117S18TR  [SOT-223]
U10  LD1117S50TR  [SOT-223]

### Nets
+1V8: C32.1 U8.2(Vout) U8.4(Tab)
+3V3: C41.1 JP5.1(COMMON) SB8.2 U8.3(Vin)
+5V: C29.1 JP2.2 JP2.4 JP2.6 R7.2 U7.3(Vin)
E5V: C35.1 JP2.1 U10.2(Vout) U10.4(Tab)
GND: C29.2 C32.2 C35.2 C36.2 C37.2 C41.2 JP1.1(COMMON) JP1.2(NO) LD5.2(K) U7.1 U8.1 U10.1
U5V_ST_LINK: JP2.3
VBUS_FS1: JP2.5
VDD_MCU: JP5.2(NO)
VIN: C36.1 U10.3(Vin)
NetC37_1: C37.1 SB8.1 U7.2(Vout) U7.4(Tab)
NetLD5_1: LD5.1(A) R7.1

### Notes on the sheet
- (near C36) Arduino power pin
- Open solder bridge if supplied
  from pin1 of extension connector

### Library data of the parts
C29 C32 C35-C37 = Cap Pol1: Polarized Capacitor (Radial); Ordered by: Subcon
C41 = Cap: as C42 on sheet Memory
JP1 = JP2: Manuf_1: SAMTEC; Ordered by: Subcon; Silkscreen: GND; Assembly: with jumper
JP2 = Header 3X2: Header, 3-Pin, Dual row; Manuf_1: SAMTEC; Ordered by: Subcon; Silkscreen: E5V:pins1,2 STLK: pins3,4 USB: pins 5,6; Assembly: 3,4 closed
JP5 = JP2: Manuf_1: SAMTEC; Ordered by: Subcon; Assembly: with jumper; Silkscreen: IDD
LD5 = LED2: Typical RED, GREEN, YELLOW, AMBER GaAs LED; Ordered by: Subcon; ECCN_US/EU: EAR99/NEC; Silkscreen: 5V
R7 = res1: Resistor; Value: 1K; Ordered by: Subcon
SB8 = Circuit Breaker: as SB1 on sheet Peripherals
U7 = LD1117S33TR: LOW DROP FIXED AND ADJUSTABLE POSITIVE VOLTAGE REGULATORS (3.3 Volts); Provided: ST; ECCN_US/EU: EAR99/NEC; Ref St: 9176186
U8 = LD1117: Ordered by: ST; ECCN_US/EU: EAR99/NEC; Ref St: 9176180
U10 = LD1117: Ordered by: ST; ECCN_US/EU: EAR99/NEC; Ref St: 9176133

## Sheet ST_LINK_V2-1.SCHDOC: ST-LINK/V2-1
size A4; Date: 9/24/2014; Author: P.A.; CompanyName: STMicroelectronics; Organization: Microcontrollers Division; Address1: 12, Rue Jules HOROWITZ; Address2: 38019 Grenoble; Address3: FRANCE; DocumentNumber: 13; Revision: B-07; SheetNumber: 13; SheetTotal: 13; Project: STM32F469I-DISCO
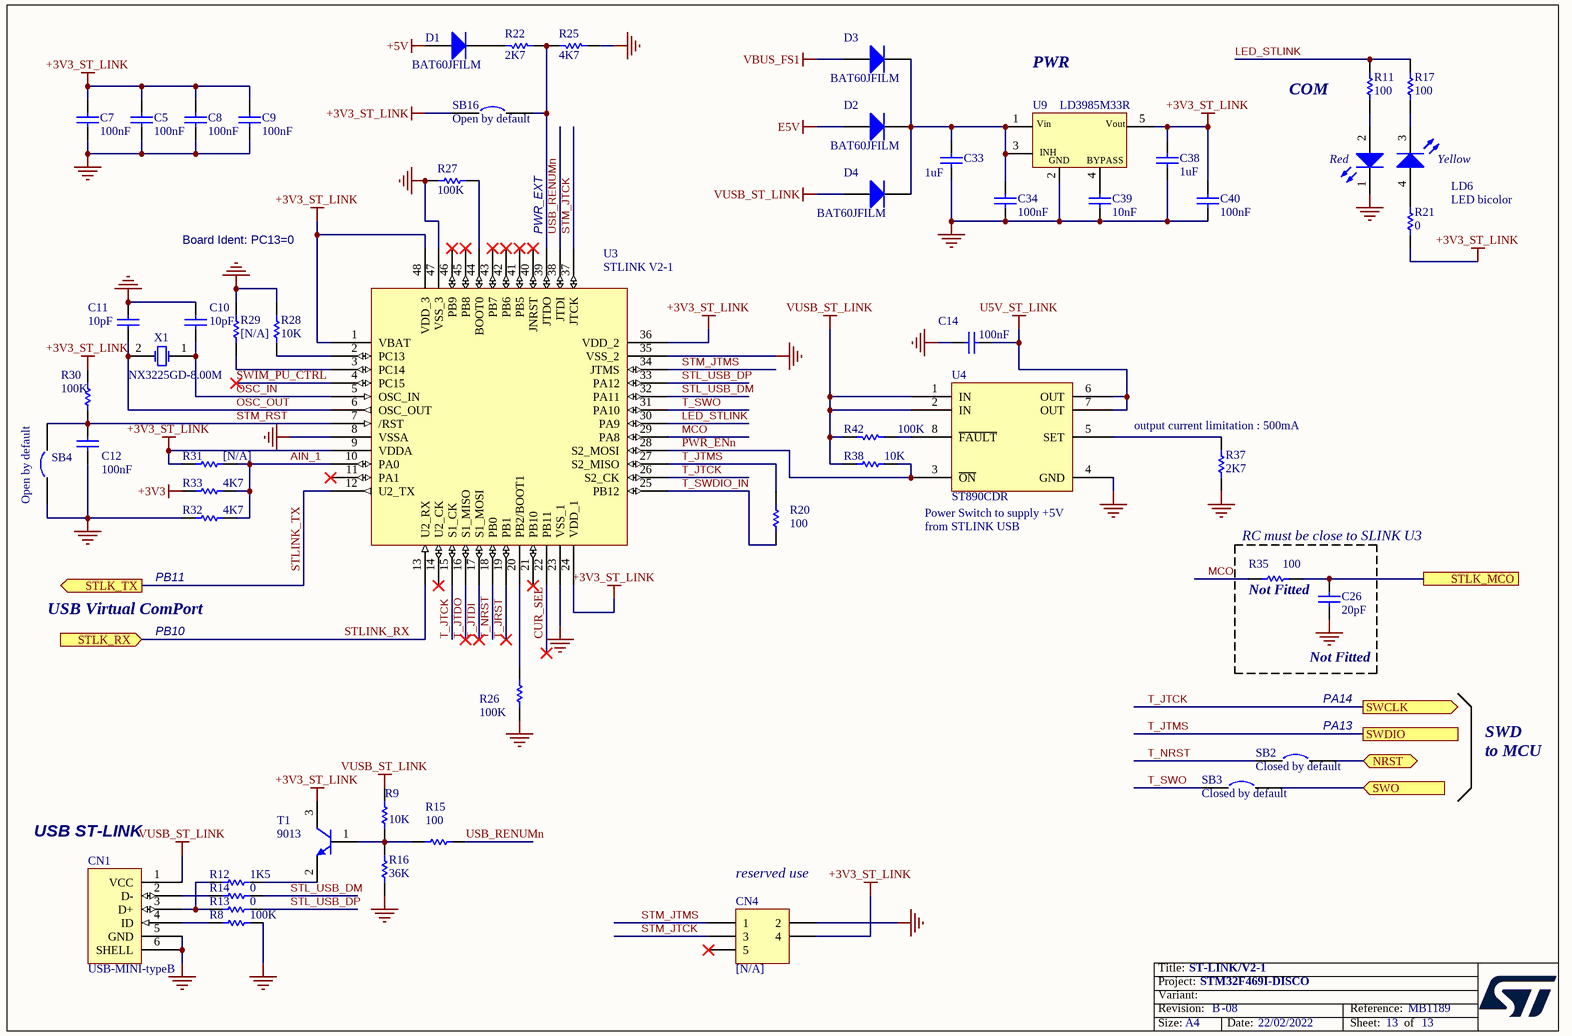
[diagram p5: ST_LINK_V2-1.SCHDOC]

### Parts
C5  100nF  [0402C]
C7  100nF  [0402C]
C8  100nF  [0402C]
C9  100nF  [0402C]
C10  10pF  [0603C]
C11  10pF  [0603C]
C12  100nF  [0402C]
C14  100nF  [0402C]
C26  20pF  [0603C]
C33  1uF  [0603C]
C34  100nF  [0402C]
C38  1uF  [0603C]
C39  10nF  [0603C]
C40  100nF  [0402C]
CN1  USB-MINI-typeB  [MINIUSB_AB_5SM_RA]
CN4  [N/A]  [HDR_2X3-1_2R54-6]
D1  BAT60JFILM  [SOD-323]
D2  BAT60JFILM  [SOD-323]
D3  BAT60JFILM  [SOD-323]
D4  BAT60JFILM  [SOD-323]
LD6  LED bicolor  [LED2_3528]
R8  100K  [0603R]
R9  10K  [0402R]
R11  100  [0603R]
R12  1K5  [0603R]
R13  0  [0603R]
R14  0  [0603R]
R15  100  [0603R]
R16  36K  [0603R]
R17  100  [0603R]
R20  100  [0603R]
R21  0  [0603R]
R22  2K7  [0603R]
R25  4K7  [0603R]
R26  100K  [0603R]
R27  100K  [0603R]
R28  10K  [0402R]
R29  [N/A]  [0603R]
R30  100K  [0603R]
R31  [N/A]  [0603R]
R32  4K7  [0603R]
R33  4K7  [0603R]
R35  100  [0603R]
R37  2K7  [0603R]
R38  10K  [0402R]
R42  100K  [0603R]
SB2  Closed by default  [SB_0603]
SB3  Closed by default  [SB_0603]
SB4  Open by default  [SB_0603]
SB16  Open by default  [SB_0603]
T1  9013  [SOT-23]
U3  STLINK V2-1  [LQFP48_0R5_9X9]
U4  ST890CDR  [SOIC8_1R27_4R9X6]
U9  LD3985M33R  [SOT23-5]
X1  NX3225GD-8.00M  [XTAL_2SM_3R2X2R5_H1]

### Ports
NRST (bidir), STLK_MCO, STLK_RX (in), STLK_TX (out), SWCLK (out), SWDIO, SWO (in)

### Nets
+3V3: R33.1
+3V3_ST_LINK: C5.2 C7.2 C8.2 C9.2 C38.1 C40.2 CN4.4 R21.2 R30.2 R31.1 SB16.1 T1.3(C) U3.1(VBAT) U3.9(VDDA) U3.24(VDD_1) U3.36(VDD_2) U3.48(VDD_3) U9.5(Vout)
+5V: D1.1(A)
E5V: D2.1(A)
GND: C5.1 C7.1 C8.1 C9.1 C10.2 C11.2 C12.1 C14.1 C26.2 C33.1 C34.1 C38.2 C39.1 C40.1 CN1.5(GND) CN1.6(SHELL) CN4.2 LD6.1(RED_cathode) R8.2 R16.1 R25.2 R26.1 R27.1 R28.1 R29.1 R32.1 R37.2 SB4.1 U3.8(VSSA) U3.23(VSS_1) U3.35(VSS_2) U3.47(VSS_3) U4.4(GND) U9.2(GND)
U5V_ST_LINK: C14.2 U4.6(OUT) U4.7(OUT)
VBUS_FS1: D3.1(A)
VUSB_ST_LINK: CN1.1(VCC) D4.1(A) R9.2 R38.1 R42.1 U4.1(IN) U4.2(IN)
AIN_1: R31.2 R32.2 R33.2 U3.10(PA0)
CUR_SEL: U3.22(PB11)
LED_STLINK: R11.1 R17.1 U3.30(PA9)
MCO: R35.1 U3.29(PA8)
NRST: SB2.2 ; port NRST
OSC_IN: C10.1 U3.5(OSC_IN) X1.1(OSC1)
OSC_OUT: C11.1 U3.6(OSC_OUT) X1.2(OSC2)
PWR_ENn: R38.2 U3.28(S2_MOSI) U4.3(~{ON})
STL_USB_DM: R14.2 U3.32(PA11)
STL_USB_DP: R13.2 U3.33(PA12)
STLINK_RX: U3.13(U2_RX) ; port STLK_RX  [project net PB10]
STLINK_TX: U3.12(U2_TX) ; port STLK_TX  [project net PB11]
STM_JTCK: CN4.3 U3.37(JTCK)
STM_JTMS: CN4.1 U3.34(JTMS)
STM_RST: C12.2 R30.1 SB4.2 U3.7(/RST)
SWIM_PU_CTRL: U3.4(PC15)
T_JRST: U3.19(PB1)
T_JTCK: U3.15(S1_CK) U3.26(S2_CK) ; port SWCLK  [project net PA14]
T_JTDI: U3.17(S1_MOSI)
T_JTDO: U3.16(S1_MISO)
T_JTMS: R20.2 U3.27(S2_MISO) ; port SWDIO  [project net PA13]
T_NRST: SB2.1 U3.18(PB0)
T_SWDIO_IN: R20.1 U3.25(PB12)
T_SWO: SB3.1 U3.31(PA10)
USB_RENUMn: R15.2 U3.38(JTDI)
NetC26_1: C26.1 R35.2 ; port STLK_MCO
NetC33_2: C33.2 C34.2 D2.2(K) D3.2(K) D4.2(K) U9.1(Vin) U9.3(CE)
NetC39_2: C39.2 U9.4(BYPASS)
NetCN1_2: CN1.2(D-) R14.1
NetCN1_3: CN1.3(D+) R12.1 R13.1
NetCN1_4: CN1.4(ID) R8.1
NetD1_2: D1.2(K) R22.1
NetLD6_2: LD6.2(Red_anode) R11.2
NetLD6_3: LD6.3(YellowGreen_cathode) R17.2
NetLD6_4: LD6.4(YellowGreen_anode) R21.1
NetR9_1: R9.1 R15.1 R16.2 T1.1(B)
NetR12_2: R12.2 T1.2(E)
NetR22_2: R22.2 R25.1 SB16.2 U3.39(JTDO)
NetR26_2: R26.2 U3.20(PB2/BOOT1)
NetR27_2: R27.2 U3.44(BOOT0)
NetR28_2: R28.2 U3.2(PC13)
NetR29_2: R29.2 U3.3(PC14)
NetR37_1: R37.1 U4.5(SET)
NetR42_2: R42.2 U4.8(~{FAULT})
NetSB3_2: SB3.2 ; port SWO

Not connected (* = marked no-connect by the designer): CN4 5*; U3 11(PA1)* 14(U2_CK)* 21(PB10)* 40(JNRST)* 41(PB5)* 42(PB6)* 43(PB7)* 45(PB8)* 46(PB9)*

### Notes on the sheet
- PWR
- COM
- Board Ident: PC13=0
- PWR_EXT
- (near R37) output current limitation : 500mA
- PB11
- (near U4) Power Switch to supply +5V from STLINK USB
- RC must be close to SLINK U3
- USB Virtual ComPort
- PB10
- Not Fitted
- (near C26) Not Fitted
- PA14
- (near SB2) PA13
- SWD
  to MCU
- (near CN1) USB ST-LINK
- (near CN4) reserved use

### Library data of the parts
C5 C7-C9 C12 C14 C34 C40 = Capacitor_ST: Capacitor 0402 / 0603 / 0805; Ordered by: Subcon
C10 C11 = Capacitor_ST: Capacitor 0402 / 0603 / 0805; Value: 100nF; Ordered by: Subcon
C26 = Cap_20pF_NPO_5%_0402: Capacitor,20pF,50V,NPO,5%,0402,YAGEO; Order: CC0402JRNPO9BN200; Fitted: NO; Ordered by: Subcon
C33 C38 = CAP SMD 0603  X5R 1µF 25V 10%: Capacitor; Value: 1µF; Rated voltage: 25V; Tolerance: 10%; Ordered by: Subcon
C39 = CAP SMD 0603  X7R 10000PF 50V 10%: 0603  X7R 10NF; Order code RS: 2040779; Rated voltage: 50V; Tolerance: 10%; Ordered by: Subcon
CN1 = USB-MINI-typeB connector: Manuf_Part_1: 5075BMR-05-SM; Manuf_Part_2: 218205M1110T; Manuf_2: lyconn; Ordered by: Subcon; Silkscreen: USB ST-LINK
CN4 = Header 3X2: Header, 3-Pin, Dual row; Fitted: NO; Ordered by: Subcon
D1-D4 = BAT60JFILM: Provided: ST; ECCN_US/EU: EAR99/NEC; Ref St: 9151097
LD6 = HSMF-A201-A00J1: Ordered by: Subcon; ECCN_US/EU: EAR99/NEC; Silkscreen: COM
R8 = res1: Resistor; Value: 1K; Ordered by: Subcon
R9 R11 R16 R17 R21 R22 R25 R42 = Res1: Resistor; Value: 1K; Ordered by: Subcon
R12-R14 R20 = Resistor_ST: Resistor; Value: 10K; Ordered by: Subcon
R15 R26 R27 R30 R32 R33 R35 R37 = Resistor_ST: Resistor 0402 / 0603 / 0805; Value: 10K; Ordered by: Subcon
R28 R38 = Resistor_ST: Resistor; Ordered by: Subcon
R29 R31 = Resistor_ST: Resistor 0402 / 0603 / 0805; Value: 10K; Fitted: NO; Ordered by: Subcon
SB2 SB3 = Circuit Breaker: as SB1 on sheet Peripherals
SB4 SB16 = Circuit Breaker: Ordered by: Subcon; Comments: Solder bridge; Fitted: NO
T1 = NPN: NPN Bipolar Transistor; Manuf_Part_1: MMBT9013; Code - JEDEC: TO-226-AA; Ordered by: Subcon; ECCN_US/EU: EAR99/NEC
U3 = STM32F10x(48pin): Manuf_Part_1: STM32F103CBT6; Ordered by: ST; ECCN_US/EU: 3A991A2/NEC; Ref St: 9175111
U4 = ST890CDR: Ordered by: ST; Ref St: 9172002; ECCN_US/EU: EAR99/NEC
U9 = LD3985M33R: Ultra low drop-low noise BiCMOS voltage, regulators low ESR capacitors compatible; Manuf_1: ST; Ref St: 9176161; ECCN_US/EU: EAR99/NEC
X1 = XTAL_8M_NX3225GD: Crystal 8Mhz, 8pF, -+50PPM, SMD; Manuf_1: NDK; Manuf_Part_1: NX3225GD 8MHz EXS00A-CG04874; Manuf_Part_2: NX3225GD-8.000M-STD-CRA-3; ECCN_US/EU: EAR99/NEC; NDK Ref: X3127326; Ref St: 9157029; Provided: ST

## Sheet MCU.SchDoc: MCU
size A3; Date: 9/24/2014; Author: P.A.; CompanyName: STMicroelectronics; Organization: Microcontrollers Division; Address1: 12, Rue Jules HOROWITZ; Address2: 38019 Grenoble; Address3: FRANCE; DocumentNumber: 3; Revision: B-07; SheetNumber: 3; SheetTotal: 13; Project: STM32F469I-DISCO
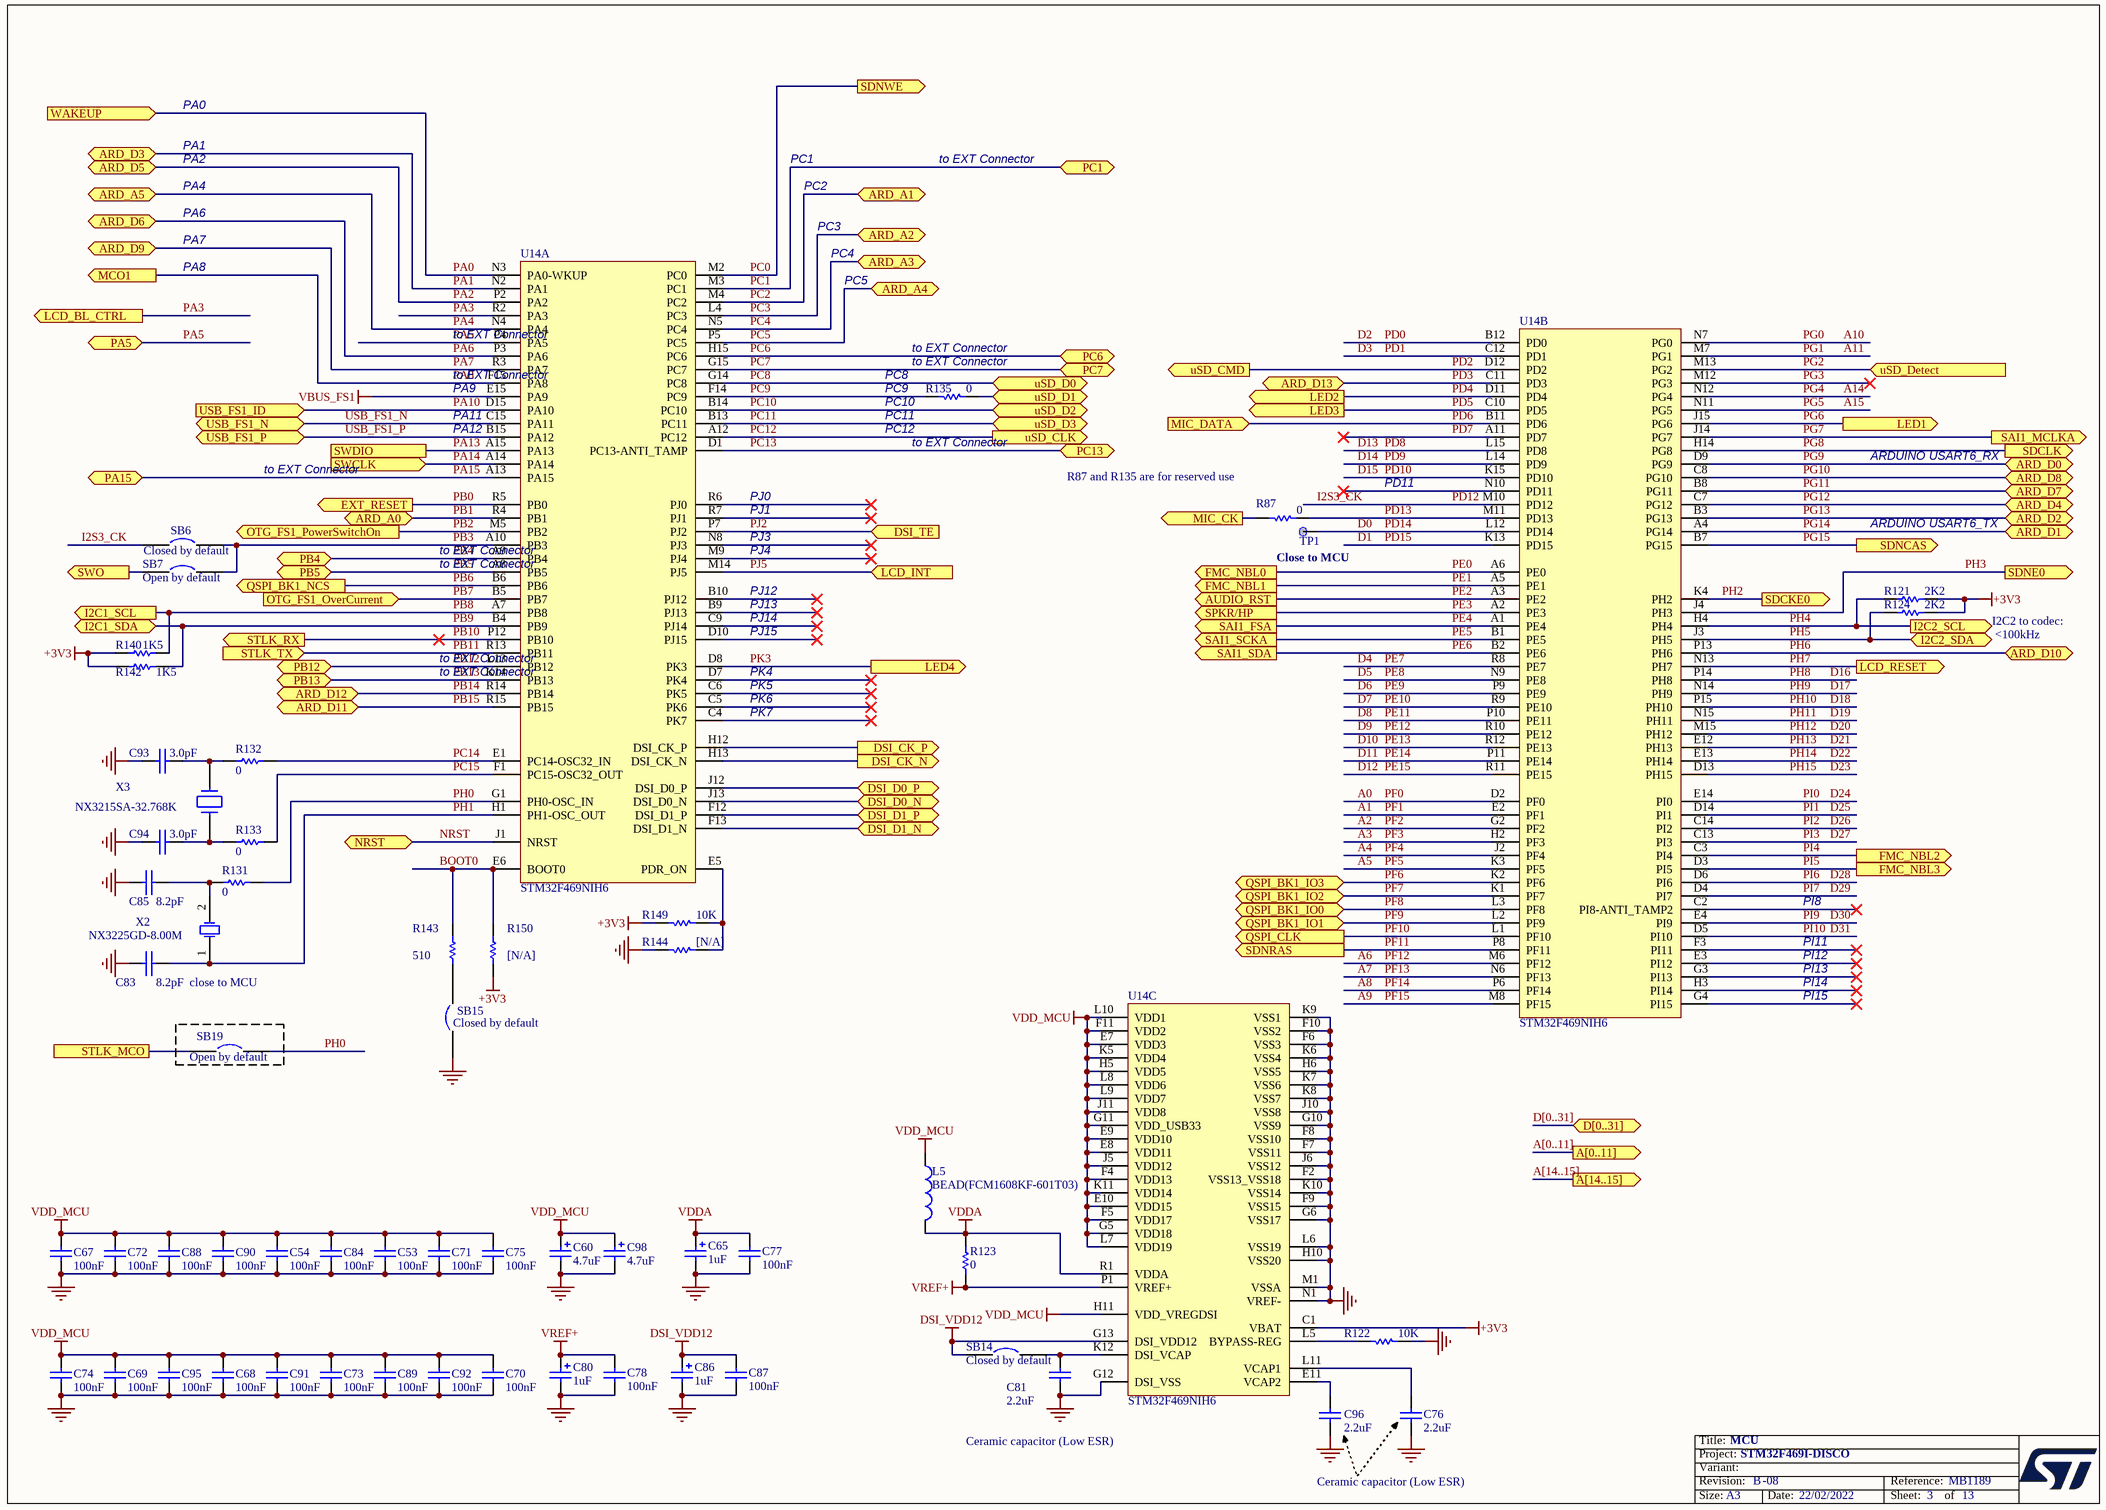
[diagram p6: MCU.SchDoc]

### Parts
C53  100nF  [0402C]
C54  100nF  [0402C]
C60  4.7uF  [TAN-A]
C65  1uF  [TAN-A]
C67  100nF  [0402C]
C68  100nF  [0402C]
C69  100nF  [0402C]
C70  100nF  [0402C]
C71  100nF  [0402C]
C72  100nF  [0402C]
C73  100nF  [0402C]
C74  100nF  [0402C]
C75  100nF  [0402C]
C76  2.2uF  [1206C]
C77  100nF  [0402C]
C78  100nF  [0402C]
C80  1uF  [TAN-A]
C81  2.2uF  [1206C]
C83  8.2pF  [0603C]
C84  100nF  [0402C]
C85  8.2pF  [0603C]
C86  1uF  [TAN-A]
C87  100nF  [0402C]
C88  100nF  [0402C]
C89  100nF  [0402C]
C90  100nF  [0402C]
C91  100nF  [0402C]
C92  100nF  [0402C]
C93  3.0pF  [0603C]
C94  3.0pF  [0603C]
C95  100nF  [0402C]
C96  2.2uF  [1206C]
C98  4.7uF  [TAN-A]
L5  BEAD(FCM1608KF-601T03)  [0603L]
R87  0  [0603R]
R121  2K2  [0603R]
R122  10K  [0402R]
R123  0  [0603R]
R124  2K2  [0603R]
R131  0  [0603R]
R132  0  [0603R]
R133  0  [0603R]
R135  0  [0603R]
R140  1K5  [0603R]
R142  1K5  [0603R]
R143  510  [0603R]
R144  [N/A]  [0603R]
R149  10K  [0402R]
R150  [N/A]  [0603R]
SB6  Closed by default  [SB_0603]
SB7  Open by default  [SB_0603]
SB14  Closed by default  [SB_0603]
SB15  Closed by default  [SB_0603]
SB19  Open by default  [SB_0603]
TP1  TP  [TP_C40]  (value not drawn)
U14  STM32F469NIH6  [BGA216_0R8_13X13]  (parts A,B,C of 3)
X2  NX3225GD-8.00M  [XTAL_2SM_3R2X2R5_H1]
X3  NX3215SA-32.768K  [XTAL_2SM_3R2X1R5]

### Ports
A[0..11] (out), A[14..15] (out), ARD_A0 (bidir), ARD_A1 (bidir), ARD_A2 (bidir), ARD_A3 (bidir), ARD_A4 (bidir), ARD_A5 (bidir), ARD_D0 (bidir), ARD_D1 (bidir), ARD_D2 (bidir), ARD_D3 (bidir), ARD_D4 (bidir), ARD_D5 (bidir), ARD_D6 (bidir), ARD_D7 (bidir), ARD_D8 (bidir), ARD_D9 (bidir), ARD_D10 (bidir), ARD_D11 (bidir), ARD_D12 (bidir), ARD_D13 (bidir), AUDIO_RST (out), D[0..31] (bidir), DSI_CK_N (out), DSI_CK_P (out), DSI_D0_N (bidir), DSI_D0_P (bidir), DSI_D1_N (bidir), DSI_D1_P (bidir), DSI_TE (in), EXT_RESET (out), FMC_NBL0 (out), FMC_NBL1 (out), FMC_NBL2 (out), FMC_NBL3 (out), I2C1_SCL (out), I2C1_SDA (bidir), I2C2_SCL (out), I2C2_SDA (bidir), LCD_BL_CTRL (out), LCD_INT (in), LCD_RESET (out), LED1 (out), LED2 (out), LED3 (out), LED4 (out), MCO1 (out), MIC_CK (out), MIC_DATA (in), NRST (bidir), OTG_FS1_OverCurrent (in), OTG_FS1_PowerSwitchOn (out), PA5 (bidir), PA15 (bidir), PB4 (bidir), PB5 (bidir), PB12 (bidir), PB13 (bidir), PC1 (bidir), PC6 (bidir), PC7 (bidir), PC13 (bidir), QSPI_BK1_IO0 (bidir), QSPI_BK1_IO1 (bidir), QSPI_BK1_IO2 (bidir), QSPI_BK1_IO3 (bidir), QSPI_BK1_NCS (out), QSPI_CLK (out), SAI1_FSA (out), SAI1_MCLKA (out), SAI1_SCKA (out), SAI1_SDA (out), SDCKE0 (out), SDCLK (out), SDNCAS (out), SDNE0 (out), SDNRAS (out), SDNWE (out), SPKR/HP (out), STLK_MCO, STLK_RX (out), STLK_TX (in), SWCLK (in), SWDIO, SWO (out), USB_FS1_ID (in), USB_FS1_N (bidir), USB_FS1_P (bidir), uSD_CLK (out), uSD_CMD (out), uSD_D0 (bidir), uSD_D1 (bidir), uSD_D2 (bidir), uSD_D3 (bidir), uSD_Detect (in), WAKEUP (in)

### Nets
+3V3: R121.1 R124.1 R140.1 R142.1 R149.2 R150.2 U14.C1(VBAT)
DSI_VDD12: C86.1 C87.2 SB14.1 U14.G13(DSI_VDD12)
GND: C53.2 C54.2 C60.2 C65.2 C67.2 C68.2 C69.2 C70.2 C71.2 C72.2 C73.2 C74.2 C75.2 C76.2 C77.1 C78.1 C80.2 C81.2 C83.2 C84.2 C85.2 C86.2 C87.1 C88.2 C89.2 C90.2 C91.2 C92.2 C93.2 C94.2 C95.2 C96.2 C98.2 R122.1 R144.2 SB15.1 U14.F2(VSS13_VSS18) U14.F6(VSS3) U14.F7(VSS11) U14.F8(VSS10) U14.F9(VSS15) U14.F10(VSS2) U14.G6(VSS17) U14.G10(VSS9) U14.G12(DSI_VSS) U14.H6(VSS5) U14.H10(VSS20) U14.J6(VSS12) U14.J10(VSS8) U14.K6(VSS4) U14.K7(VSS6) U14.K8(VSS7) U14.K9(VSS1) U14.K10(VSS14) U14.L6(VSS19) U14.M1(VSSA) U14.N1(VREF-)
VBUS_FS1: U14.E15(PA9)
VDD_MCU: C53.1 C54.1 C60.1 C67.1 C68.1 C69.1 C70.1 C71.1 C72.1 C73.1 C74.1 C75.1 C84.1 C88.1 C89.1 C90.1 C91.1 C92.1 C95.1 C98.1 L5.1 U14.E7(VDD3) U14.E8(VDD11) U14.E9(VDD10) U14.E10(VDD15) U14.F4(VDD13) U14.F5(VDD17) U14.F11(VDD2) U14.G5(VDD18) U14.G11(VDD_USB33) U14.H5(VDD5) U14.H11(VDD_VREGDSI) U14.J5(VDD12) U14.J11(VDD8) U14.K5(VDD4) U14.K11(VDD14) U14.L7(VDD19) U14.L8(VDD6) U14.L9(VDD7) U14.L10(VDD1)
VDDA: C65.1 C77.2 L5.2 R123.1 U14.R1(VDDA)
VREF+: C78.2 C80.1 R123.2 U14.P1(VREF+)
A0: U14.D2(PF0)  [also labelled PF0]
A1: U14.E2(PF1)  [also labelled PF1]
A2: U14.G2(PF2)  [also labelled PF2]
A3: U14.H2(PF3)  [also labelled PF3]
A4: U14.J2(PF4)  [also labelled PF4]
A5: U14.K3(PF5)  [also labelled PF5]
A6: U14.M6(PF12)  [also labelled PF12]
A7: U14.N6(PF13)  [also labelled PF13]
A8: U14.P6(PF14)  [also labelled PF14]
A9: U14.M8(PF15)  [also labelled PF15]
A10: U14.N7(PG0)  [also labelled PG0]
A11: U14.M7(PG1)  [also labelled PG1]
A14: U14.N12(PG4)  [also labelled PG4]
A15: U14.N11(PG5)  [also labelled PG5]
BOOT0: R143.1 R150.1 U14.E6(BOOT0)
D0: TP1.1 U14.L12(PD14)  [also labelled PD14]
D1: U14.K13(PD15)  [also labelled PD15]
D2: U14.B12(PD0)  [also labelled PD0]
D3: U14.C12(PD1)  [also labelled PD1]
D4: U14.R8(PE7)  [also labelled PE7]
D5: U14.N9(PE8)  [also labelled PE8]
D6: U14.P9(PE9)  [also labelled PE9]
D7: U14.R9(PE10)  [also labelled PE10]
D8: U14.P10(PE11)  [also labelled PE11]
D9: U14.R10(PE12)  [also labelled PE12]
D10: U14.R12(PE13)  [also labelled PE13]
D11: U14.P11(PE14)  [also labelled PE14]
D12: U14.R11(PE15)  [also labelled PE15]
D13: U14.L15(PD8)  [also labelled PD8]
D14: U14.L14(PD9)  [also labelled PD9]
D15: U14.K15(PD10)  [also labelled PD10]
D16: U14.P14(PH8)  [also labelled PH8]
D17: U14.N14(PH9)  [also labelled PH9]
D18: U14.P15(PH10)  [also labelled PH10]
D19: U14.N15(PH11)  [also labelled PH11]
D20: U14.M15(PH12)  [also labelled PH12]
D21: U14.E12(PH13)  [also labelled PH13]
D22: U14.E13(PH14)  [also labelled PH14]
D23: U14.D13(PH15)  [also labelled PH15]
D24: U14.E14(PI0)  [also labelled PI0]
D25: U14.D14(PI1)  [also labelled PI1]
D26: U14.C14(PI2)  [also labelled PI2]
D27: U14.C13(PI3)  [also labelled PI3]
D28: U14.D6(PI6)  [also labelled PI6]
D29: U14.D4(PI7)  [also labelled PI7]
D30: U14.E4(PI9)  [also labelled PI9]
D31: U14.D5(PI10)  [also labelled PI10]
HSSI_CLK_N: U14.H13(DSI_CK_N) ; port DSI_CK_N
HSSI_CLK_P: U14.H12(DSI_CK_P) ; port DSI_CK_P
HSSI_D0_N: U14.J13(DSI_D0_N) ; port DSI_D0_N
HSSI_D0_P: U14.J12(DSI_D0_P) ; port DSI_D0_P
HSSI_D1_N: U14.F13(DSI_D1_N) ; port DSI_D1_N
HSSI_D1_P: U14.F12(DSI_D1_P) ; port DSI_D1_P
I2S3_CK: SB6.1 U14.M10(PD12)  [also labelled PD12]
NRST: U14.J1(NRST) ; port NRST
PA0: U14.N3(PA0-WKUP) ; port WAKEUP
PA1: U14.N2(PA1) ; port ARD_D3
PA2: U14.P2(PA2) ; port ARD_D5
PA3: U14.R2(PA3) ; port LCD_BL_CTRL  [project net LCD_BL_CTRL]
PA4: U14.N4(PA4) ; port ARD_A5
PA5: U14.P4(PA5) ; port PA5
PA6: U14.P3(PA6) ; port ARD_D6
PA7: U14.R3(PA7) ; port ARD_D9
PA8: U14.F15(PA8) ; port MCO1
PA10: U14.D15(PA10) ; port USB_FS1_ID
PA13: U14.A15(PA13) ; port SWDIO
PA14: U14.A14(PA14) ; port SWCLK
PA15: U14.A13(PA15) ; port PA15
PB0: U14.R5(PB0) ; port EXT_RESET
PB1: U14.R4(PB1) ; port ARD_A0
PB2: U14.M5(PB2) ; port OTG_FS1_PowerSwitchOn
PB3: SB6.2 SB7.2 U14.A10(PB3)
PB4: U14.A9(PB4) ; port PB4
PB5: U14.A8(PB5) ; port PB5
PB6: U14.B6(PB6) ; port QSPI_BK1_NCS
PB7: U14.B5(PB7) ; port OTG_FS1_OverCurrent
PB8: R140.2 U14.A7(PB8) ; port I2C1_SCL  [project net I2C1_SCL]
PB9: R142.2 U14.B4(PB9) ; port I2C1_SDA  [project net I2C1_SDA]
PB10: U14.P12(PB10) ; port STLK_RX
PB11: U14.R13(PB11) ; port STLK_TX
PB12: U14.L13(PB12) ; port PB12
PB13: U14.K14(PB13) ; port PB13
PB14: U14.R14(PB14) ; port ARD_D12
PB15: U14.R15(PB15) ; port ARD_D11
PC0: U14.M2(PC0) ; port SDNWE
PC1: U14.M3(PC1) ; port PC1
PC2: U14.M4(PC2) ; port ARD_A1
PC3: U14.L4(PC3) ; port ARD_A2
PC4: U14.N5(PC4) ; port ARD_A3
PC5: U14.P5(PC5) ; port ARD_A4
PC6: U14.H15(PC6) ; port PC6
PC7: U14.G15(PC7) ; port PC7
PC8: U14.G14(PC8) ; port uSD_D0
PC9: R135.1 U14.F14(PC9)
PC10: U14.B14(PC10) ; port uSD_D2
PC11: U14.B13(PC11) ; port uSD_D3
PC12: U14.A12(PC12) ; port uSD_CLK
PC13: U14.D1(PC13-ANTI_TAMP) ; port PC13
PC14: R132.2 U14.E1(PC14-OSC32_IN)
PC15: R133.2 U14.F1(PC15-OSC32_OUT)
PD2: U14.D12(PD2) ; port uSD_CMD
PD3: U14.C11(PD3) ; port ARD_D13
PD4: U14.D11(PD4) ; port LED2
PD5: U14.C10(PD5) ; port LED3
PD6: U14.B11(PD6) ; port MIC_DATA
PD7: U14.A11(PD7)
PD13: R87.2 U14.M11(PD13)
PE0: U14.A6(PE0) ; port FMC_NBL0
PE1: U14.A5(PE1) ; port FMC_NBL1
PE2: U14.A3(PE2) ; port AUDIO_RST  [project net AUDIO_RST]
PE3: U14.A2(PE3) ; port SPKR/HP
PE4: U14.A1(PE4) ; port SAI1_FSA
PE5: U14.B1(PE5) ; port SAI1_SCKA
PE6: U14.B2(PE6) ; port SAI1_SDA
PF6: U14.K2(PF6) ; port QSPI_BK1_IO3
PF7: U14.K1(PF7) ; port QSPI_BK1_IO2
PF8: U14.L3(PF8) ; port QSPI_BK1_IO0
PF9: U14.L2(PF9) ; port QSPI_BK1_IO1
PF10: U14.L1(PF10) ; port QSPI_CLK
PF11: U14.P8(PF11) ; port SDNRAS
PG2: U14.M13(PG2) ; port uSD_Detect
PG3: U14.M12(PG3)
PG6: U14.J15(PG6) ; port LED1
PG7: U14.J14(PG7) ; port SAI1_MCLKA
PG8: U14.H14(PG8) ; port SDCLK
PG9: U14.D9(PG9) ; port ARD_D0
PG10: U14.C8(PG10) ; port ARD_D8
PG11: U14.B8(PG11) ; port ARD_D7
PG12: U14.C7(PG12) ; port ARD_D4
PG13: U14.B3(PG13) ; port ARD_D2
PG14: U14.A4(PG14) ; port ARD_D1
PG15: U14.B7(PG15) ; port SDNCAS
PH0: R131.1 SB19.2 U14.G1(PH0-OSC_IN)
PH1: C83.1 U14.H1(PH1-OSC_OUT) X2.1(OSC1)
PH2: U14.K4(PH2) ; port SDCKE0
PH3: U14.J4(PH3) ; port SDNE0
PH4: R121.2 U14.H4(PH4) ; port I2C2_SCL  [project net I2C2_SCL]
PH5: R124.2 U14.J3(PH5) ; port I2C2_SDA  [project net I2C2_SDA]
PH6: U14.P13(PH6) ; port ARD_D10
PH7: U14.N13(PH7) ; port LCD_RESET  [project net LCD_RST]
PI4: U14.C3(PI4) ; port FMC_NBL2
PI5: U14.D3(PI5) ; port FMC_NBL3
PJ2: U14.P7(PJ2) ; port DSI_TE
PJ5: U14.M14(PJ5) ; port LCD_INT  [project net LCD_INT]
PK3: U14.D8(PK3) ; port LED4
USB_FS1_N: U14.C15(PA11) ; port USB_FS1_N
USB_FS1_P: U14.B15(PA12) ; port USB_FS1_P
NetC26_1: SB19.1 ; port STLK_MCO
NetC76_1: C76.1 U14.L11(VCAP1)
NetC81_1: C81.1 SB14.2 U14.K12(DSI_VCAP)
NetC85_1: C85.1 R131.2 X2.2(OSC2)
NetC93_1: C93.1 R132.1 X3.1
NetC94_1: C94.1 R133.1 X3.2
NetC96_1: C96.1 U14.E11(VCAP2)
NetCN9_8: R135.2 ; port uSD_D1
NetR87_1: R87.1 ; port MIC_CK
NetR122_2: R122.2 U14.L5(BYPASS-REG)
NetR143_2: R143.2 SB15.2
NetR144_1: R144.1 R149.1 U14.E5(PDR_ON)
NetSB3_2: SB7.1 ; port SWO

Not connected (* = marked no-connect by the designer): U14 B9(PJ13)* B10(PJ12)* C2(PI8-ANTI_TAMP2)* C4(PK7)* C5(PK6)* C6(PK5)* C9(PJ14)* D7(PK4)* D10(PJ15)* E3(PI12)* F3(PI11)* G3(PI13)* G4(PI15)* H3(PI14)* M9(PJ4)* N8(PJ3)* N10(PD11)* R6(PJ0)* R7(PJ1)*

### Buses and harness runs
bus A[0..11] = port A[0..11]
bus A[14..15] = port A[14..15]
bus D[0..31] = port D[0..31]

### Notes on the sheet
- PA0
- PA1
- PA2
- PC1
- to EXT Connector
- PA6
- PA7
- PA4
- PC2
- PC3
- PA8
- PC4
- PC5
- (near R135) PC8
- (near R135) to EXT Connector
- (near U14) PA11
- (near U14) PA12
- (near U14) PA9
- (near R135) PC9
- (near R135) PC10
- (near R135) PC11
- (near R135) PC12
- PJ1
- PJ0
- (near R87) R87 and R135 are for reserved use
- PD11
- ARDUINO USART6_RX
- PJ4
- PJ3
- Close to MCU
- ARDUINO USART6_TX
- PJ15
- PJ13
- PJ12
- PJ14
- I2C2 to codec:
  <100kHz
- PK7
- PK6
- PK5
- PK4
- PI8
- close to MCU
- PI14
- PI13
- PI12
- PI11
- PI15
- Ceramic capacitor (Low ESR)

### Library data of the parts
C53 C54 C67-C75 C83-C85 C88-C95 = CAP: Capacitor; Ordered by: Subcon
C60 C98 = Cap Pol1: Polarized Capacitor (Radial); Value: 47uF; Ordered by: Subcon
C65 C80 C86 = Cap Pol1: Polarized Capacitor (Radial); Value: 10uF; Ordered by: Subcon
C76-C78 C81 C87 C96 = Cap: as C42 on sheet Memory
L5 = Inductor: Value: 100uH; Ordered by: Subcon
R87 R121-R124 R131-R133 R135 R140 R142 R149 = Res1: Resistor; Value: 1K; Ordered by: Subcon
R143 = res1: Resistor; Value: 1K; Ordered by: Subcon
R144 = Res1: Resistor; Value: 1K; Ordered by: Subcon; Fitted: NO
R150 = res1: Resistor; Value: 1K; Ordered by: Subcon; Fitted: NO
SB6 SB14 SB15 = Circuit Breaker: as SB1 on sheet Peripherals
SB7 SB19 = Circuit Breaker: as SB4 on sheet ST_LINK_V2-1
TP1 = TP: Ordered by: Subcon
U14 = Manta_Dragon_TFBGA216: Manuf_Part_1: STM32F469NIH6U cut 1.0; Ordered by: ST; Ref St: 9175177; ECCN_US/EU: 3A991A2/NEC
X2 = XTAL_8M_NX3225GD: as X1 on sheet ST_LINK_V2-1
X3 = XTAL_32K_NX3215SA: Crystal 32.768kHz, 6pF, -+20PPM, R=50K, SMD; Manuf_1: NDK; Manuf_Part_1: NX3215SA 32.768KHz EXS00A-MU00525; ECCN_US/EU: EAR99/NEC; Ref St: 9157034; NDK Ref: X3101802; Provided: ST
